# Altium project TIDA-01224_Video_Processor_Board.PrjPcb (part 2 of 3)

## Sheet TIDA-010224_Video_Processor_P02_OA7000_Image_Sensor.SchDoc: TIDA-010224_P02_OA7000_Image_Sensor
size A2; Date: Not shown in title block; ApprovedBy: Not shown in title block; CheckedBy: Not shown in title block; Author: Not shown in title block; CompanyName: Not shown in title block; DrawnBy: Sakshi Markhedkar; Engineer: Not shown in title block; Organization: Not shown in title block; Address1: Not shown in title block; Address2: Not shown in title block; Address3: Not shown in title block; Address4: Not shown in title block; DocumentNumber: 3; Revision: Use project parameter SCH_Rev; SheetNumber: 3; SheetTotal: 6; PageSetup: Record=PageOptions¦CenterHorizontal=True¦CenterVertical=True¦PrintScale=1.00¦XCorrection=1.00¦YCorrection=1.00¦PrintKind=0¦BorderSize=5000000¦LeftOffset=0¦BottomOffset=0¦Orientation=2¦PaperLength=1000¦PaperWidth=1000¦Scale=100¦PaperSource=15¦PrintQuality=600¦MediaType=1¦DitherType=10¦PaperKind=Letter¦PrintScaleMode=1
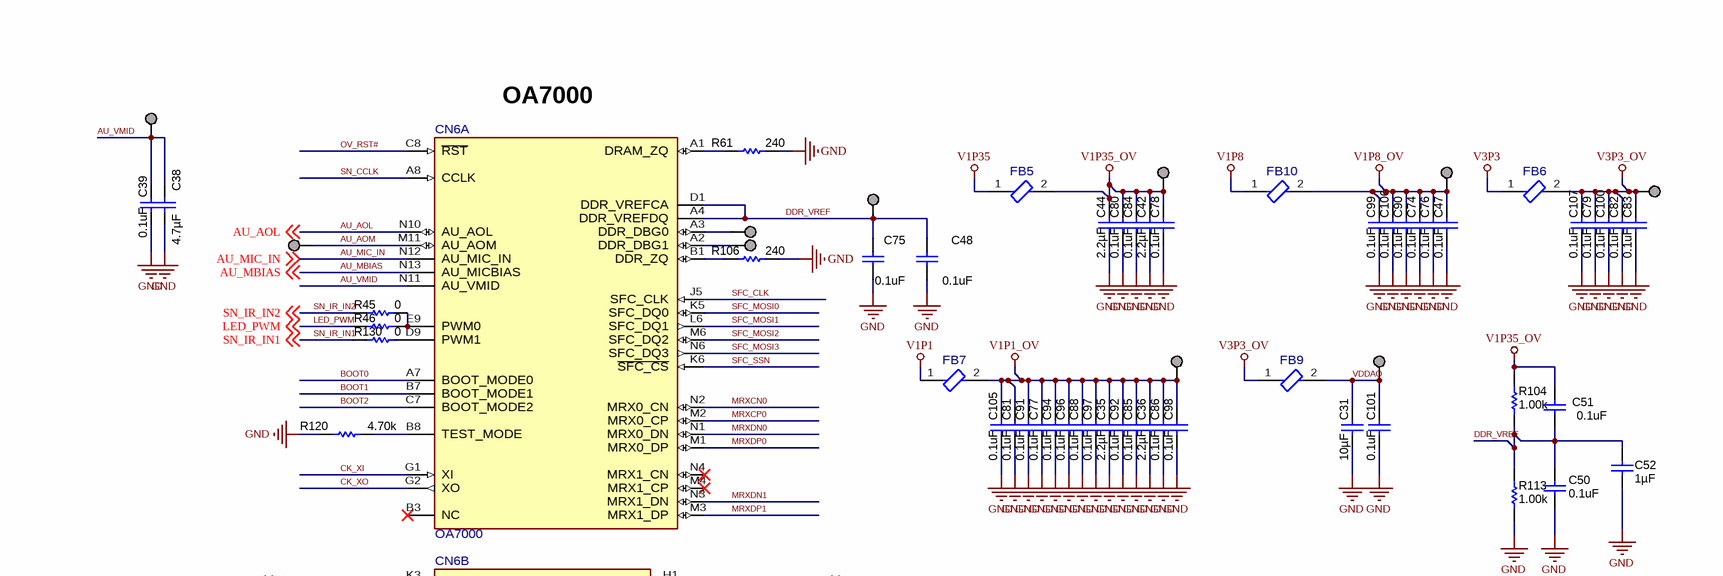
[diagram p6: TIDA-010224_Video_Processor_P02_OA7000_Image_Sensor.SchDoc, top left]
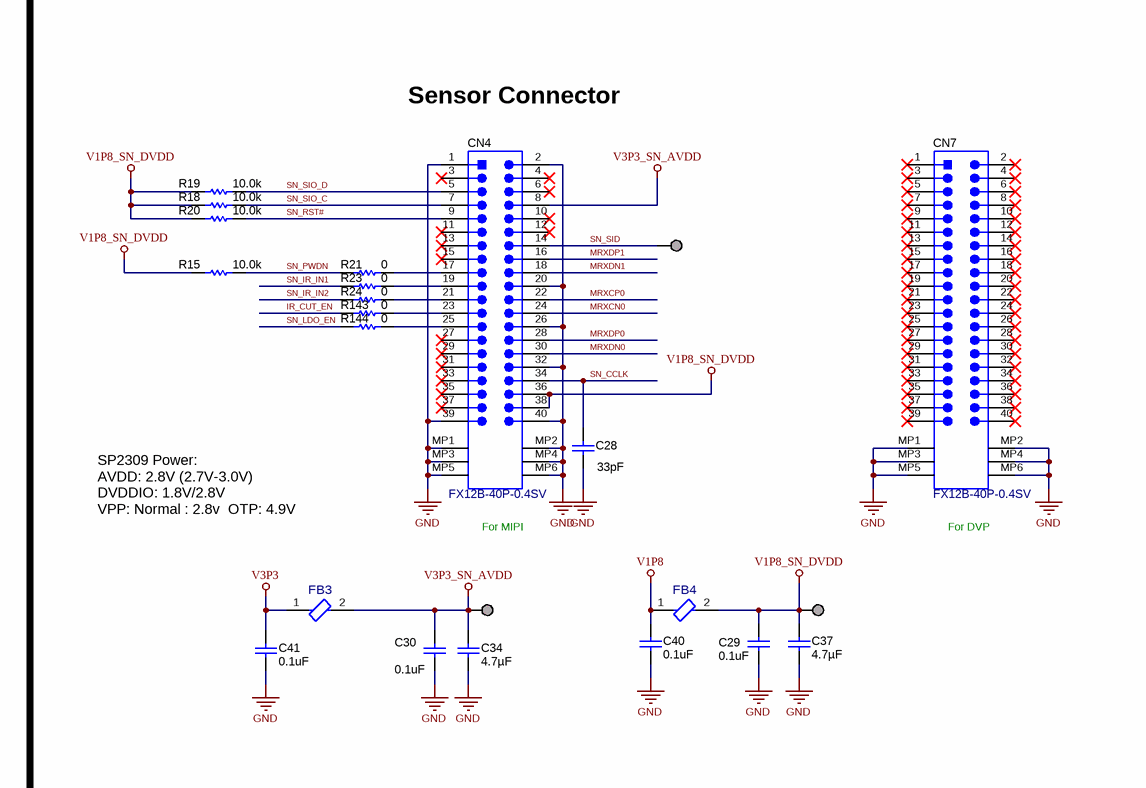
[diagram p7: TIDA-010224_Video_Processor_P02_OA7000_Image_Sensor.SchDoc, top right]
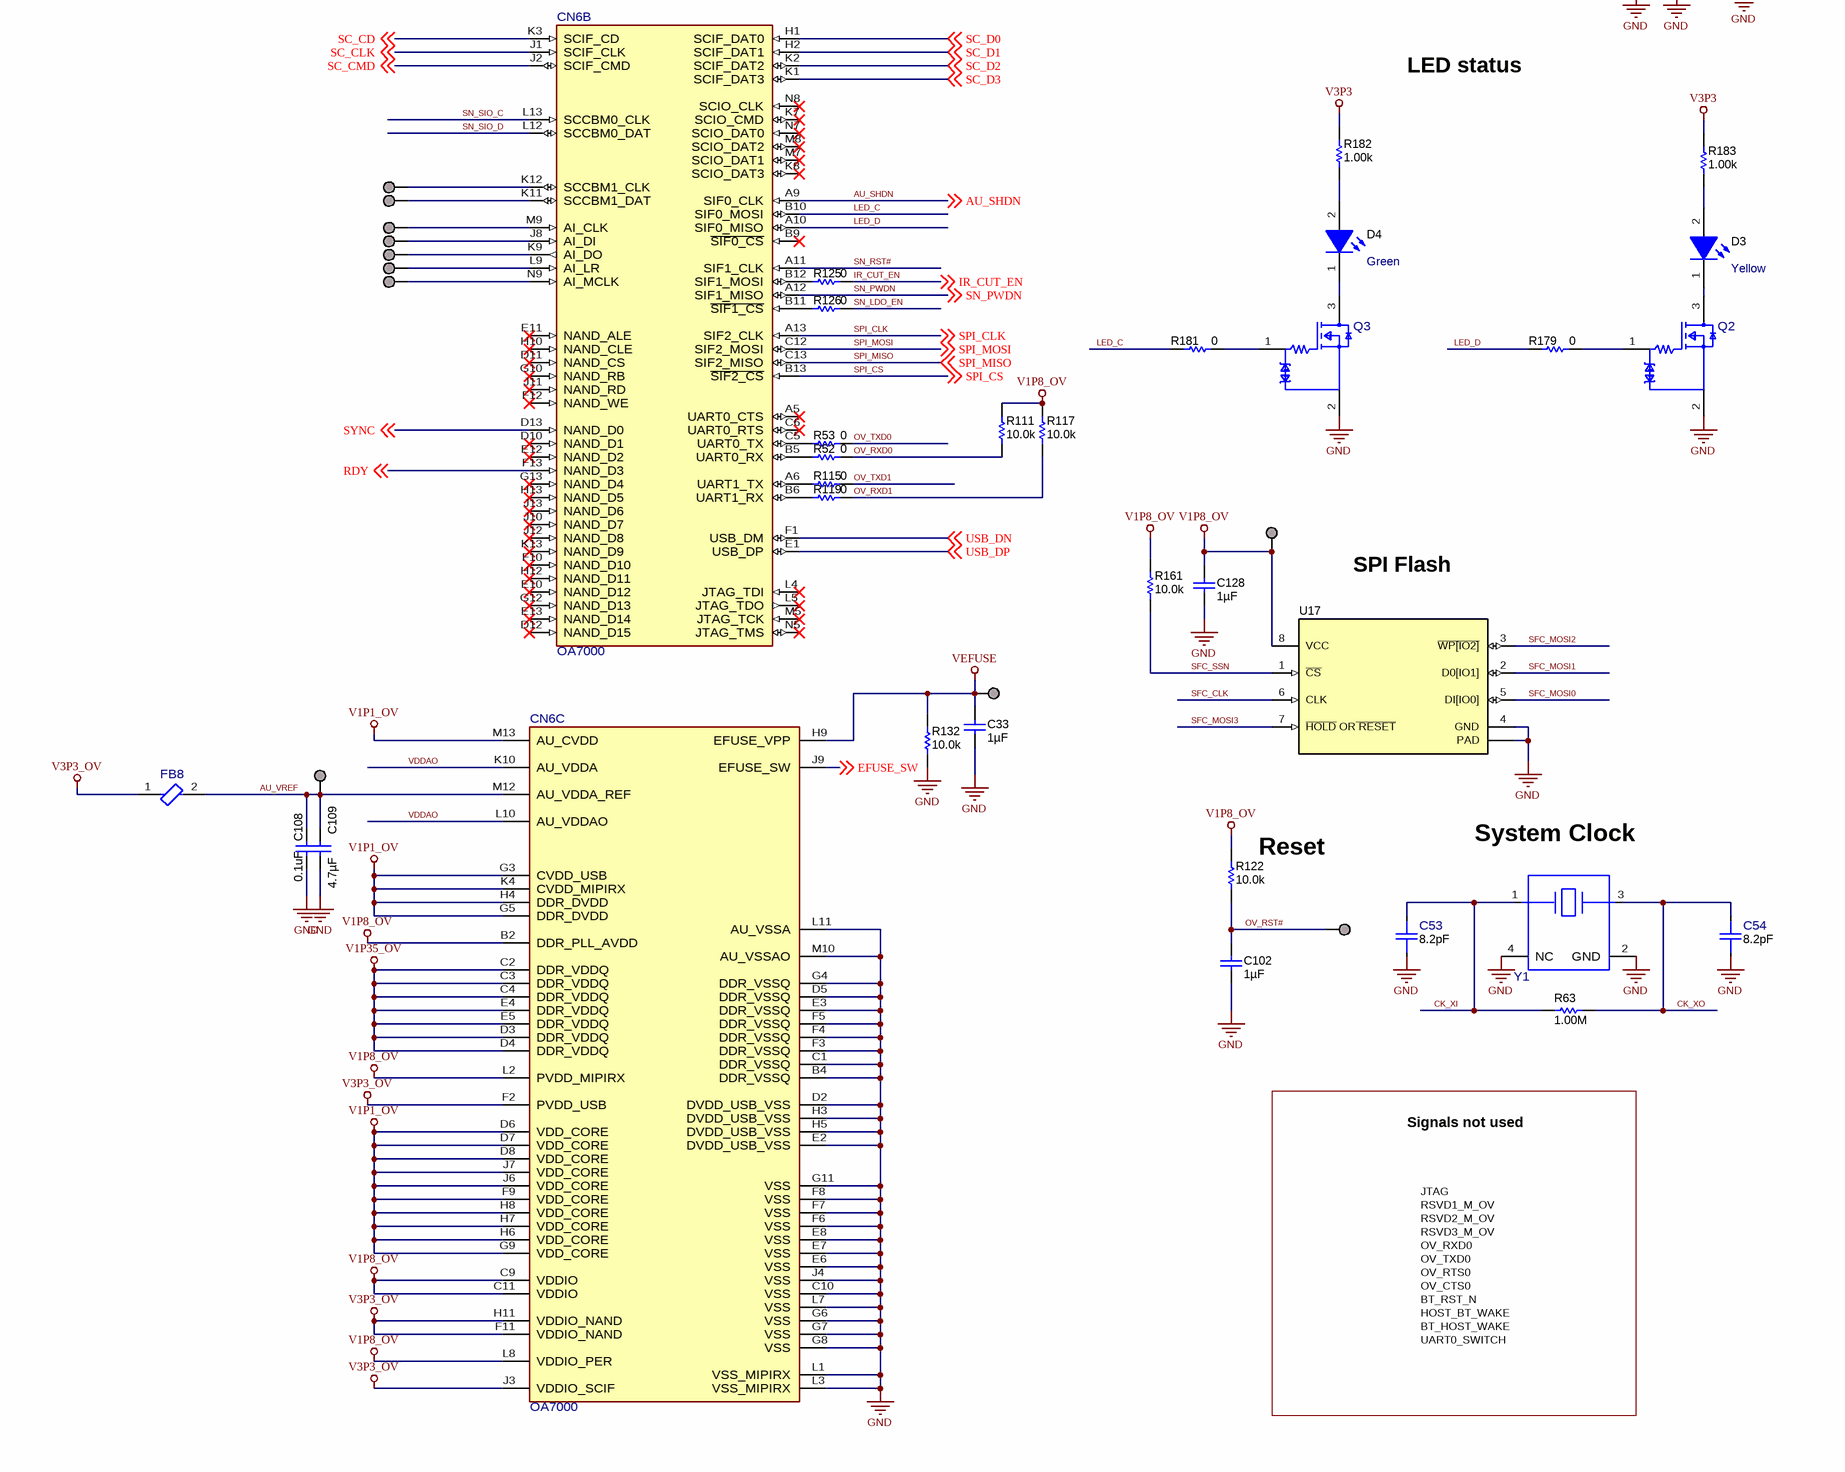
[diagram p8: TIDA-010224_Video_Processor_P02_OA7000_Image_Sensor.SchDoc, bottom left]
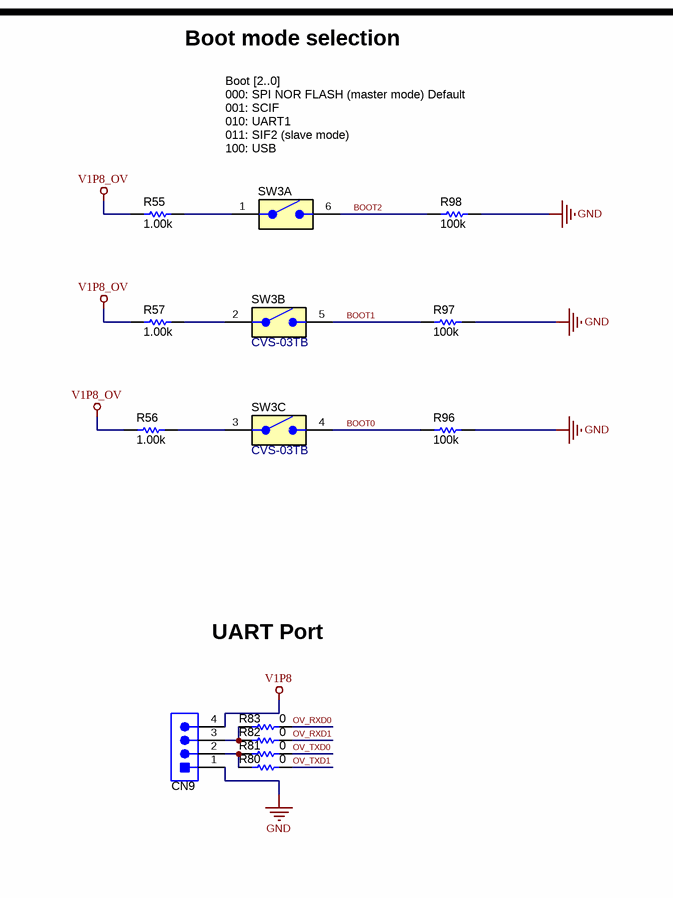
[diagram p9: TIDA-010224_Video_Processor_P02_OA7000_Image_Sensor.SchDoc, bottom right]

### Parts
AOM  TP_SM_1MM  [TP_SM_1MM]  (value not drawn)  (no BOM)
AVDD  TP_SM_1MM  [TP_SM_1MM]  (value not drawn)  (no BOM)
C  TP_SM_1MM  [TP_SM_1MM]  (value not drawn)  (no BOM)
C28  ValueDisplayed: 33pF  [0402]  (hidden comment: C1005C0G1H330J050BA)
C29  value 0.1uF  [0402]  (hidden comment: GRM155R71C104KA88D)
C30  value 0.1uF  [0402]  (hidden comment: GRM155R71C104KA88D)
C31  Cap_F: 10µF  [0805_HV]  (hidden comment: CL21B106KOQNNNE)
C33  Cap_F: 1µF  [0603]  (hidden comment: GCM188R71C105MA64D)
C34  Cap_F: 4.7µF  [0603]  (hidden comment: GRM188Z71C475KE21D)
C35  Cap_F: 2.2µF  [0603]  (hidden comment: GRM188Z71C225KE43)
C36  Cap_F: 2.2µF  [0603]  (hidden comment: GRM188Z71C225KE43)
C37  Cap_F: 4.7µF  [0603]  (hidden comment: GRM188Z71C475KE21D)
C38  Cap_F: 4.7µF  [0603]  (hidden comment: GRM188Z71C475KE21D)
C39  ValueDisplayed: 0.1uF  [0201]  (hidden comment: GRM033Z71C104KE14D)
C40  value 0.1uF  [0402]  (hidden comment: GRM155R71C104KA88D)
C41  value 0.1uF  [0402]  (hidden comment: GRM155R71C104KA88D)
C42  Cap_F: 2.2µF  [0603]  (hidden comment: GRM188Z71C225KE43)
C44  Cap_F: 2.2µF  [0603]  (hidden comment: GRM188Z71C225KE43)
C47  ValueDisplayed: 0.1uF  [0201]  (hidden comment: GRM033Z71C104KE14D)
C48  ValueDisplayed: 0.1uF  [0201]  (hidden comment: GRM033Z71C104KE14D)
C50  ValueDisplayed: 0.1uF  [0201]  (hidden comment: GRM033Z71C104KE14D)
C51  ValueDisplayed: 0.1uF  [0201]  (hidden comment: GRM033Z71C104KE14D)
C52  Cap_F: 1µF  [0603]  (hidden comment: GCM188R71C105MA64D)
C53  ValueDisplayed: 8.2pF  [FP-GRM1555C1H8R2BA01D_0402-MFG]  (hidden comment: GRM1555C1H8R2BA01D)
C54  ValueDisplayed: 8.2pF  [FP-GRM1555C1H8R2BA01D_0402-MFG]  (hidden comment: GRM1555C1H8R2BA01D)
C74  ValueDisplayed: 0.1uF  [0201]  (hidden comment: GRM033Z71C104KE14D)
C75  ValueDisplayed: 0.1uF  [0201]  (hidden comment: GRM033Z71C104KE14D)
C76  ValueDisplayed: 0.1uF  [0201]  (hidden comment: GRM033Z71C104KE14D)
C77  ValueDisplayed: 0.1uF  [0201]  (hidden comment: GRM033Z71C104KE14D)
C78  ValueDisplayed: 0.1uF  [0201]  (hidden comment: GRM033Z71C104KE14D)
C79  ValueDisplayed: 0.1uF  [0201]  (hidden comment: GRM033Z71C104KE14D)
C80  ValueDisplayed: 0.1uF  [0201]  (hidden comment: GRM033Z71C104KE14D)
C81  ValueDisplayed: 0.1uF  [0201]  (hidden comment: GRM033Z71C104KE14D)
C82  ValueDisplayed: 0.1uF  [0201]  (hidden comment: GRM033Z71C104KE14D)
C83  ValueDisplayed: 0.1uF  [0201]  (hidden comment: GRM033Z71C104KE14D)
C84  ValueDisplayed: 0.1uF  [0201]  (hidden comment: GRM033Z71C104KE14D)
C85  ValueDisplayed: 0.1uF  [0201]  (hidden comment: GRM033Z71C104KE14D)
C86  ValueDisplayed: 0.1uF  [0201]  (hidden comment: GRM033Z71C104KE14D)
C88  ValueDisplayed: 0.1uF  [0201]  (hidden comment: GRM033Z71C104KE14D)
C90  ValueDisplayed: 0.1uF  [0201]  (hidden comment: GRM033Z71C104KE14D)
C91  ValueDisplayed: 0.1uF  [0201]  (hidden comment: GRM033Z71C104KE14D)
C92  ValueDisplayed: 0.1uF  [0201]  (hidden comment: GRM033Z71C104KE14D)
C94  ValueDisplayed: 0.1uF  [0201]  (hidden comment: GRM033Z71C104KE14D)
C96  ValueDisplayed: 0.1uF  [0201]  (hidden comment: GRM033Z71C104KE14D)
C97  ValueDisplayed: 0.1uF  [0201]  (hidden comment: GRM033Z71C104KE14D)
C98  ValueDisplayed: 0.1uF  [0201]  (hidden comment: GRM033Z71C104KE14D)
C99  ValueDisplayed: 0.1uF  [0201]  (hidden comment: GRM033Z71C104KE14D)
C100  ValueDisplayed: 0.1uF  [0201]  (hidden comment: GRM033Z71C104KE14D)
C101  ValueDisplayed: 0.1uF  [0201]  (hidden comment: GRM033Z71C104KE14D)
C102  Cap_F: 1µF  [0603]  (hidden comment: GCM188R71C105MA64D)
C105  ValueDisplayed: 0.1uF  [0201]  (hidden comment: GRM033Z71C104KE14D)
C106  ValueDisplayed: 0.1uF  [0201]  (hidden comment: GRM033Z71C104KE14D)
C107  ValueDisplayed: 0.1uF  [0201]  (hidden comment: GRM033Z71C104KE14D)
C108  ValueDisplayed: 0.1uF  [0201]  (hidden comment: GRM033Z71C104KE14D)
C109  Cap_F: 4.7µF  [0603]  (hidden comment: GRM188Z71C475KE21D)
C128  Cap_F: 1µF  [0603]  (hidden comment: GCM188R71C105MA64D)
CLK  TP_SM_1MM  [TP_SM_1MM]  (value not drawn)  (no BOM)
CN4  FX12B-40P-0.4SV  [Hirose_FX12B-40P-0_4SV]
CN6  OA7000  [FP-OA7000_BGA169-IPC_C]  (parts A,B,C of 3)
CN7  FX12B-40P-0.4SV  [Hirose_FX12B-40P-0_4SV]
CN9  GRPB041VWVN-RC  [Sullins_GRPB041VWVN-RC]  (value not drawn)
D  TP_SM_1MM  [TP_SM_1MM]  (value not drawn)  (no BOM)
D3  value Yellow  [WL-SMCW_YELLOW]  (hidden comment: 150060YS75000)
D4  value Green  [WL-SMCW_GREEN]  (hidden comment: 150060GS75000)
DBG0  TP_SM_1MM  [TP_SM_1MM]  (value not drawn)  (no BOM)
DBG1  TP_SM_1MM  [TP_SM_1MM]  (value not drawn)  (no BOM)
DI  TP_SM_1MM  [TP_SM_1MM]  (value not drawn)  (no BOM)
DO  TP_SM_1MM  [TP_SM_1MM]  (value not drawn)  (no BOM)
DVDD  TP_SM_1MM  [TP_SM_1MM]  (value not drawn)  (no BOM)
FB3  BLM18KG121TN1D  [FP-BLM18KG121TN1D_0603-MFG]  (value not drawn)
FB4  BLM18KG121TN1D  [FP-BLM18KG121TN1D_0603-MFG]  (value not drawn)
FB5  BLM18KG121TN1D  [FP-BLM18KG121TN1D_0603-MFG]  (value not drawn)
FB6  BLM18KG121TN1D  [FP-BLM18KG121TN1D_0603-MFG]  (value not drawn)
FB7  BLM18KG121TN1D  [FP-BLM18KG121TN1D_0603-MFG]  (value not drawn)
FB8  BLM18KG121TN1D  [FP-BLM18KG121TN1D_0603-MFG]  (value not drawn)
FB9  BLM18KG121TN1D  [FP-BLM18KG121TN1D_0603-MFG]  (value not drawn)
FB10  BLM18KG121TN1D  [FP-BLM18KG121TN1D_0603-MFG]  (value not drawn)
LR  TP_SM_1MM  [TP_SM_1MM]  (value not drawn)  (no BOM)
MCLK  TP_SM_1MM  [TP_SM_1MM]  (value not drawn)  (no BOM)
OV_1.1V  TP_SM_1MM  [TP_SM_1MM]  (value not drawn)  (no BOM)
OV_1.8V  TP_SM_1MM  [TP_SM_1MM]  (value not drawn)  (no BOM)
OV_1.35V  TP_SM_1MM  [TP_SM_1MM]  (value not drawn)  (no BOM)
OV_3.3V  TP_SM_1MM  [TP_SM_1MM]  (value not drawn)  (no BOM)
Q2  NTS4001NT1G  [FP-NTS4001NT1G_SC-70-MFG]  (value not drawn)
Q3  NTS4001NT1G  [FP-NTS4001NT1G_SC-70-MFG]  (value not drawn)
R15  ValueDisplayed: 10.0k  [0402]  (hidden comment: ERJPA2F1002X)
R18  ValueDisplayed: 10.0k  [0402]  (hidden comment: ERJPA2F1002X)
R19  ValueDisplayed: 10.0k  [0402]  (hidden comment: ERJPA2F1002X)
R20  ValueDisplayed: 10.0k  [0402]  (hidden comment: ERJPA2F1002X)
R21  ValueDisplayed: 0  [0402S]  (hidden comment: RC0402JR-070RL)
R23  ValueDisplayed: 0  [0402S]  (hidden comment: RC0402JR-070RL)
R24  ValueDisplayed: 0  [0402S]  (hidden comment: RC0402JR-070RL)
R45  ValueDisplayed: 0  [0402S]  (hidden comment: RC0402JR-070RL)
R46  ValueDisplayed: 0  [0402S]  (hidden comment: RC0402JR-070RL)
R52  ValueDisplayed: 0  [0402S]  (hidden comment: RC0402JR-070RL)
R53  ValueDisplayed: 0  [0402S]  (hidden comment: RC0402JR-070RL)
R55  ValueDisplayed: 1.00k  [0402]  (hidden comment: CRCW04021K00FKED)
R56  ValueDisplayed: 1.00k  [0402]  (hidden comment: CRCW04021K00FKED)
R57  ValueDisplayed: 1.00k  [0402]  (hidden comment: CRCW04021K00FKED)
R61  ValueDisplayed: 240  [0402]  (hidden comment: ERJ-2RKF2400X)
R63  ValueDisplayed: 1.00M  [0402]  (hidden comment: RMCF0402FT1M00)
R80  ValueDisplayed: 0  [0402S]  (hidden comment: RC0402JR-070RL)
R81  ValueDisplayed: 0  [0402S]  (hidden comment: RC0402JR-070RL)
R82  ValueDisplayed: 0  [0402S]  (hidden comment: RC0402JR-070RL)
R83  ValueDisplayed: 0  [0402S]  (hidden comment: RC0402JR-070RL)
R96  ValueDisplayed: 100k  [0201]  (hidden comment: RC0201FR-07100KL)
R97  ValueDisplayed: 100k  [0201]  (hidden comment: RC0201FR-07100KL)
R98  ValueDisplayed: 100k  [0201]  (hidden comment: RC0201FR-07100KL)
R104  ValueDisplayed: 1.00k  [0402]  (hidden comment: CRCW04021K00FKED)
R106  ValueDisplayed: 240  [0402]  (hidden comment: ERJ-2RKF2400X)
R111  ValueDisplayed: 10.0k  [0402]  (hidden comment: ERJPA2F1002X)
R113  ValueDisplayed: 1.00k  [0402]  (hidden comment: CRCW04021K00FKED)
R115  ValueDisplayed: 0  [0402S]  (hidden comment: RC0402JR-070RL)
R117  ValueDisplayed: 10.0k  [0402]  (hidden comment: ERJPA2F1002X)
R119  ValueDisplayed: 0  [0402S]  (hidden comment: RC0402JR-070RL)
R120  ValueDisplayed: 4.70k  [0402]  (hidden comment: ERJ-2RKF4701X)
R122  ValueDisplayed: 10.0k  [0402]  (hidden comment: ERJPA2F1002X)
R125  ValueDisplayed: 0  [0402S]  (hidden comment: RC0402JR-070RL)
R126  ValueDisplayed: 0  [0402S]  (hidden comment: RC0402JR-070RL)
R130  ValueDisplayed: 0  [0402S]  (hidden comment: RC0402JR-070RL)
R132  ValueDisplayed: 10.0k  [0402]  (hidden comment: ERJPA2F1002X)
R143  ValueDisplayed: 0  [0402S]  (hidden comment: RC0402JR-070RL)
R144  ValueDisplayed: 0  [0402S]  (hidden comment: RC0402JR-070RL)
R161  ValueDisplayed: 10.0k  [0402]  (hidden comment: ERJPA2F1002X)
R179  ValueDisplayed: 0  [0402S]  (hidden comment: RC0402JR-070RL)
R181  ValueDisplayed: 0  [0402S]  (hidden comment: RC0402JR-070RL)
R182  ValueDisplayed: 1.00k  [0402]  (hidden comment: CRCW04021K00FKED)
R183  ValueDisplayed: 1.00k  [0402]  (hidden comment: CRCW04021K00FKED)
RST  TP_SM_1MM  [TP_SM_1MM]  (value not drawn)  (no BOM)
SID  TP_SM_1MM  [TP_SM_1MM]  (value not drawn)  (no BOM)
SW3  CVS-03TB  [SW_CVS-03B]  (value not drawn)  (parts A,B,C of 3)
U17  MX25U12835FZNI-10G‎  [Winbond-WSON6x5_Code P]  (value not drawn)
VCC_MEM  TP_SM_1MM  [TP_SM_1MM]  (value not drawn)  (no BOM)
VDDAO  TP_SM_1MM  [TP_SM_1MM]  (value not drawn)  (no BOM)
VeFuse  TP_SM_1MM  [TP_SM_1MM]  (value not drawn)  (no BOM)
VMID  TP_SM_1MM  [TP_SM_1MM]  (value not drawn)  (no BOM)
VREF  TP_SM_1MM  [TP_SM_1MM]  (value not drawn)  (no BOM)
VREF_AU  TP_SM_1MM  [TP_SM_1MM]  (value not drawn)  (no BOM)
Y1  ‎8Q-24.000MEEV-T‎  [FP-8Q-24.000MEIV-T_SMD-4-MFG]  (value not drawn)

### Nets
GND: C28.2 C29.2 C30.2 C31.1 C33.2 C34.2 C35.2 C36.2 C37.2 C38.2 C39.1 C40.2 C41.2 C42.2 C44.2 C47.1 C48.1 C50.1 C52.2 C53.1 C54.1 C74.1 C75.1 C76.1 C77.1 C78.1 C79.1 C80.1 C81.1 C82.1 C83.1 C84.1 C85.1 C86.1 C88.1 C90.1 C91.1 C92.1 C94.1 C96.1 C97.1 C98.1 C99.1 C100.1 C101.1 C102.2 C105.1 C106.1 C107.1 C108.1 C109.2 C128.2 CN4.1 CN4.2 CN4.20 CN4.26 CN4.32 CN4.39 CN4.40 CN4.MP1 CN4.MP2 CN4.MP3 CN4.MP4 CN4.MP5 CN4.MP6 CN6.B4(DDR_VSSQ) CN6.C1(DDR_VSSQ) CN6.C10(VSS) CN6.D2(DVDD_USB_VSS) CN6.D5(DDR_VSSQ) CN6.E2(DVDD_USB_VSS) CN6.E3(DDR_VSSQ) CN6.E6(VSS) CN6.E7(VSS) CN6.E8(VSS) CN6.F3(DDR_VSSQ) CN6.F4(DDR_VSSQ) CN6.F5(DDR_VSSQ) CN6.F6(VSS) CN6.F7(VSS) CN6.F8(VSS) CN6.G4(DDR_VSSQ) CN6.G6(VSS) CN6.G7(VSS) CN6.G8(VSS) CN6.G11(VSS) CN6.H3(DVDD_USB_VSS) CN6.H5(DVDD_USB_VSS) CN6.J4(VSS) CN6.L1(VSS_MIPIRX) CN6.L3(VSS_MIPIRX) CN6.L7(VSS) CN6.L11(AU_VSSA) CN6.M10(AU_VSSAO) CN7.MP1 CN7.MP2 CN7.MP3 CN7.MP4 CN7.MP5 CN7.MP6 CN9.1 Q2.2(Source) Q3.2(Source) R61.2 R96.2 R97.2 R98.2 R106.2 R113.1 R120.1 R132.1 U17.4(GND) U17.9(PAD) Y1.2(GND) Y1.4(NC)
V1P1: FB7.1
V1P1_OV: C35.1 C36.1 C77.2 C81.2 C85.2 C86.2 C88.2 C91.2 C92.2 C94.2 C96.2 C97.2 C98.2 C105.2 CN6.D6(VDD_CORE) CN6.D7(VDD_CORE) CN6.D8(VDD_CORE) CN6.F9(VDD_CORE) CN6.G3(CVDD_USB) CN6.G5(DDR_DVDD) CN6.G9(VDD_CORE) CN6.H4(DDR_DVDD) CN6.H6(VDD_CORE) CN6.H7(VDD_CORE) CN6.H8(VDD_CORE) CN6.J6(VDD_CORE) CN6.J7(VDD_CORE) CN6.K4(CVDD_MIPIRX) CN6.M13(AU_CVDD) FB7.2 OV_1.1V.1
V1P8: C40.1 CN9.4 FB4.1 FB10.1
V1P8_OV: C47.2 C74.2 C76.2 C90.2 C99.2 C106.2 C128.1 CN6.B2(DDR_PLL_AVDD) CN6.C9(VDDIO) CN6.C11(VDDIO) CN6.L2(PVDD_MIPIRX) CN6.L8(VDDIO_PER) FB10.2 OV_1.8V.1 R55.2 R56.2 R57.2 R111.2 R117.2 R122.2 R161.2 U17.8(VCC) VCC_MEM.1
V1P8_SN_DVDD: C29.1 C37.1 CN4.36 CN4.38 DVDD.1 FB4.2 R15.2 R18.2 R19.2 R20.2
V1P35: FB5.1
V1P35_OV: C42.1 C44.1 C51.2 C78.2 C80.2 C84.2 CN6.C2(DDR_VDDQ) CN6.C3(DDR_VDDQ) CN6.C4(DDR_VDDQ) CN6.D3(DDR_VDDQ) CN6.D4(DDR_VDDQ) CN6.E4(DDR_VDDQ) CN6.E5(DDR_VDDQ) FB5.2 OV_1.35V.1 R104.2
V3P3: C41.1 FB3.1 FB6.1 R182.2 R183.2
V3P3_OV: C79.2 C82.2 C83.2 C100.2 C107.2 CN6.F2(PVDD_USB) CN6.F11(VDDIO_NAND) CN6.H11(VDDIO_NAND) CN6.J3(VDDIO_SCIF) FB6.2 FB8.1 FB9.1 OV_3.3V.1
V3P3_SN_AVDD: AVDD.1 C30.1 C34.1 CN4.8 FB3.2
VEFUSE: C33.1 CN6.H9(EFUSE_VPP) R132.2 VeFuse.1
AU_AOL: CN6.N10(AU_AOL) ; off-sheet AU_AOL
AU_AOM: AOM.1 CN6.M11(AU_AOM)
AU_MBIAS: CN6.N13(AU_MICBIAS) ; off-sheet AU_MBIAS
AU_MIC_IN: CN6.N12(AU_MIC_IN) ; off-sheet AU_MIC_IN
AU_SHDN: CN6.A9(SIF0_CLK) ; off-sheet AU_SHDN
AU_VMID: C38.1 C39.2 CN6.N11(AU_VMID) VMID.1
AU_VREF: C108.2 C109.1 CN6.M12(AU_VDDA_REF) FB8.2 VREF_AU.1
BOOT0: CN6.A7(BOOT_MODE0) R96.1 SW3.4
BOOT1: CN6.B7(BOOT_MODE1) R97.1 SW3.5
BOOT2: CN6.C7(BOOT_MODE2) R98.1 SW3.6
CK_XI: C53.2 CN6.G1(XI) R63.1 Y1.1
CK_XO: C54.2 CN6.G2(XO) R63.2 Y1.3
DDR_VREF: C48.2 C50.2 C51.1 C52.1 C75.2 CN6.A4(DDR_VREFDQ) CN6.D1(DDR_VREFCA) R104.1 R113.2 VREF.1
EFUSE_SW: CN6.J9(EFUSE_SW) ; off-sheet EFUSE_SW
IR_CUT_EN: R125.2 R143.1 ; off-sheet IR_CUT_EN
LED_C: CN6.B10(SIF0_MOSI) R181.1
LED_D: CN6.A10(SIF0_MISO) R179.1
LED_PWM: R46.1 ; off-sheet LED_PWM
MRXCN0: CN4.24 CN6.N2(MRX0_CN)
MRXCP0: CN4.22 CN6.M2(MRX0_CP)
MRXDN0: CN4.30 CN6.N1(MRX0_DN)
MRXDN1: CN4.18 CN6.N3(MRX1_DN)
MRXDP0: CN4.28 CN6.M1(MRX0_DP)
MRXDP1: CN4.16 CN6.M3(MRX1_DP)
OV_RST#: C102.1 CN6.C8(~{RST}) R122.1 RST.1
OV_RXD0: R52.2 R83.2 R111.1
OV_RXD1: R82.2 R117.1 R119.2
OV_TXD0: R53.2 R81.2
OV_TXD1: R80.2 R115.2
RDY: CN6.F13(NAND_D3) ; off-sheet RDY
SC_CD: CN6.K3(SCIF_CD) ; off-sheet SC_CD
SC_CLK: CN6.J1(SCIF_CLK) ; off-sheet SC_CLK
SC_CMD: CN6.J2(SCIF_CMD) ; off-sheet SC_CMD
SC_D0: CN6.H1(SCIF_DAT0) ; off-sheet SC_D0
SC_D1: CN6.H2(SCIF_DAT1) ; off-sheet SC_D1
SC_D2: CN6.K2(SCIF_DAT2) ; off-sheet SC_D2
SC_D3: CN6.K1(SCIF_DAT3) ; off-sheet SC_D3
SFC_CLK: CN6.J5(SFC_CLK) U17.6(CLK)
SFC_MOSI0: CN6.K5(SFC_DQ0) U17.5(DI[IO0])
SFC_MOSI1: CN6.L6(SFC_DQ1) U17.2(D0[IO1])
SFC_MOSI2: CN6.M6(SFC_DQ2) U17.3(~{WP[IO2]})
SFC_MOSI3: CN6.N6(SFC_DQ3) U17.7(~{HOLD}_OR~{_RESET})
SFC_SSN: CN6.K6(~{SFC_CS}) R161.1 U17.1(~{CS})
SN_CCLK: C28.1 CN4.34 CN6.A8(CCLK)
SN_IR_IN1: R23.1 R130.1 ; off-sheet SN_IR_IN1
SN_IR_IN2: R24.1 R45.1 ; off-sheet SN_IR_IN2
SN_LDO_EN: R126.2 R144.1
SN_PWDN: CN6.A12(SIF1_MISO) R15.1 R21.1 ; off-sheet SN_PWDN
SN_RST#: CN4.9 CN6.A11(SIF1_CLK) R20.1
SN_SID: CN4.14 SID.1
SN_SIO_C: CN4.7 CN6.L13(SCCBM0_CLK) R18.1
SN_SIO_D: CN4.5 CN6.L12(SCCBM0_DAT) R19.1
SPI_CLK: CN6.A13(SIF2_CLK) ; off-sheet SPI_CLK
SPI_CS: CN6.B13(~{SIF2_CS}) ; off-sheet SPI_CS
SPI_MISO: CN6.C13(SIF2_MISO) ; off-sheet SPI_MISO
SPI_MOSI: CN6.C12(SIF2_MOSI) ; off-sheet SPI_MOSI
SYNC: CN6.D13(NAND_D0) ; off-sheet SYNC
USB_DN: CN6.F1(USB_DM) ; off-sheet USB_DN
USB_DP: CN6.E1(USB_DP) ; off-sheet USB_DP
VDDAO: C31.2 C101.2 CN6.K10(AU_VDDA) CN6.L10(AU_VDDAO) FB9.2 VDDAO.1
NetC_1: C.1 CN6.K12(SCCBM1_CLK)
NetCLK_1: CLK.1 CN6.M9(AI_CLK)
NetCN4_17: CN4.17 R21.2
NetCN4_19: CN4.19 R23.2
NetCN4_21: CN4.21 R24.2
NetCN4_23: CN4.23 R143.2
NetCN4_25: CN4.25 R144.2
NetCN6_A1: CN6.A1(DRAM_ZQ) R61.1
NetCN6_A2: CN6.A2(DDR_DBG1) DBG1.1
NetCN6_A3: CN6.A3(DDR_DBG0) DBG0.1
NetCN6_A6: CN6.A6(UART1_TX) R115.1
NetCN6_B1: CN6.B1(DDR_ZQ) R106.1
NetCN6_B5: CN6.B5(UART0_RX) R52.1
NetCN6_B6: CN6.B6(UART1_RX) R119.1
NetCN6_B8: CN6.B8(TEST_MODE) R120.2
NetCN6_B11: CN6.B11(~{SIF1_CS}) R126.1
NetCN6_B12: CN6.B12(SIF1_MOSI) R125.1
NetCN6_C5: CN6.C5(UART0_TX) R53.1
NetCN6_D9: CN6.D9(PWM1) R130.2
NetCN6_E9: CN6.E9(PWM0) R45.2 R46.2
NetCN6_J8: CN6.J8(AI_DI) DI.1
NetCN6_K9: CN6.K9(AI_DO) DO.1
NetCN6_K11: CN6.K11(SCCBM1_DAT) D.1
NetCN6_L9: CN6.L9(AI_LR) LR.1
NetCN6_N9: CN6.N9(AI_MCLK) MCLK.1
NetCN9_2: CN9.2 R80.1 R81.1
NetCN9_3: CN9.3 R82.1 R83.1
NetD3_1: D3.1(K) Q2.3(Drain)
NetD3_2: D3.2(A) R183.1
NetD4_1: D4.1(K) Q3.3(Drain)
NetD4_2: D4.2(A) R182.1
NetQ2_1: Q2.1(Gate) R179.2
NetQ3_1: Q3.1(Gate) R181.2
NetR55_1: R55.1 SW3.1
NetR56_1: R56.1 SW3.3
NetR57_1: R57.1 SW3.2

Not connected (* = marked no-connect by the designer): CN4 3* 4* 6* 10* 11* 12* 13* 15* 27* 29* 31* 33* 35* 37*; CN6 A5(UART0_CTS)* B3(NC)* B9(~{SIF0_CS})* C6(UART0_RTS)* D10(NAND_D1)* D11(NAND_CS)* D12(NAND_D15)* E10(NAND_D12)* E11(NAND_ALE)* E12(NAND_D2)* E13(NAND_D14)* F10(NAND_D10)* F12(NAND_WE)* G10(NAND_RB)* G12(NAND_D13)* G13(NAND_D4)* H10(NAND_CLE)* H12(NAND_D11)* H13(NAND_D5)* J10(NAND_D7)* J11(NAND_RD)* J12(NAND_D8)* J13(NAND_D6)* K7(SCIO_CMD)* K8(SCIO_DAT3)* K13(NAND_D9)* L4(JTAG_TDI)* L5(JTAG_TDO)* M4(MRX1_CP)* M5(JTAG_TCK)* M7(SCIO_DAT1)* M8(SCIO_DAT2)* N4(MRX1_CN)* N5(JTAG_TMS)* N7(SCIO_DAT0)* N8(SCIO_CLK)*; CN7 1* 2* 3* 4* 5* 6* 7* 8* 9* 10* 11* 12* 13* 14* 15* 16* 17* 18* 19* 20* 21* 22* 23* 24* 25* 26* 27* 28* 29* 30* 31* 32* 33* 34* 35* 36* 37* 38* 39* 40*

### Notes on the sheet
- (near CN6) OA7000
- Sensor Connector
- (near CN4) For MIPI
- (near CN7) For DVP
- LED status
- SP2309 Power:
  AVDD: 2.8V (2.7V-3.0V)
  DVDDIO: 1.8V/2.8V
  VPP: Normal : 2.8v  OTP: 4.9V
- Boot mode selection
- SPI Flash
- Boot [2..0]
  000: SPI NOR FLASH (master mode) Default
  001: SCIF
  010: UART1
  011: SIF2 (slave mode)
  100: USB
- (near R122) Reset
- System Clock
- UART Port
- Signals not used
- JTAG
- RSVD1_M_OV
- RSVD2_M_OV
- RSVD3_M_OV
- OV_RXD0
- OV_TXD0
- OV_RTS0
- OV_CTS0
- BT_RST_N
- HOST_BT_WAKE
- BT_HOST_WAKE
- UART0_SWITCH

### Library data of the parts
AOM AVDD C CLK D DBG0 DBG1 DI DO DVDD LR MCLK OV_1.1V OV_1.8V OV_1.35V OV_3.3V RST SID VCC_MEM VDDAO VeFuse VMID VREF VREF_AU = CMP-0003825-1: 1mm Test Point, SMT; Manufacturer: Any
C28 = CMP-0006250-2: CAP, CERM, 33 pF, 50 V, +/- 5%, C0G/NP0, 0402; Manufacturer: TDK; TaMin_C: -55°C; Polarized: N; SizeAreaWB_mm2: 3; Value1: Unknown; U/M: EA; Value: 33pF; TaMax_C: 125°C; SizeZ_mm: 0.6; SizeX_mm: 1; SizeY_mm: 0.5; Value2: 50V; AEC Category: Q200
C29 C30 C40 C41 = Cap: CAP CER 0.1UF 16V 10% X7R 0402; Manufacturer: Murata Electronics North America
C31 = CMP-0007995-1: CAP, CERM, 10 uF, 16 V, +/- 10%, X7R, 0805; Manufacturer: Samsung Electro-Mechanics; TaMin_C: -55°C; Polarized: N; SizeAreaWB_mm2: 6.75; Value1: Unknown; U/M: EA; Value: 10uF; TaMax_C: 125°C; SizeZ_mm: 1.45; SizeX_mm: 2; SizeY_mm: 1.25; Cap_Case: 0805; Value2: 16V; SizeArea_mm2: 2.5; AEC Category: Q200
C33 C52 C102 C128 = CMP-0007137-1: CAP, CERM, 1 uF, 16 V, +/- 20%, X7R, AEC-Q200 Grade 1, 0603; Manufacturer: MuRata; TaMin_C: -55°C; Polarized: N; SizeAreaWB_mm2: 4.68; Value1: Unknown; U/M: EA; Value: 1uF; TaMax_C: 125°C; SizeZ_mm: 1; SizeX_mm: 1.6; SizeY_mm: 0.8; Value2: 16V; SizeArea_mm2: 1.28; AEC Qualified: Y; AEC Category: Q200
C34 C37 C38 C109 = CMP-0064936-4: CAP, CERM, 4.7 uF, 16 V,+/- 10%, X7R, 0603; Manufacturer: MuRata; TaMin_C: -55°C; Polarized: N; SizeAreaWB_mm2: 4.68; Value1: Unknown; U/M: EA; Value: 4.7uF; TaMax_C: 125°C; SizeZ_mm: 1; SizeX_mm: 1.6; SizeY_mm: 0.8; Value2: 16V; SizeArea_mm2: 1.28; AEC Category: Q200
C35 C36 C42 C44 = CMP-0007499-1: CAP, CERM, 2.2 uF, 16 V, +/- 10%, X7R, 0603; Manufacturer: MuRata; TaMin_C: -55°C; Polarized: N; SizeAreaWB_mm2: 4.68; Value1: Unknown; U/M: EA; Value: 2.2uF; TaMax_C: 125°C; SizeZ_mm: 1; SizeX_mm: 1.6; SizeY_mm: 0.8; Value2: 16V; SizeArea_mm2: 1.28; AEC Category: Q200
C39 C47 C48 C50 C51 C74-C86 C88 C90-C92 C94 C96-C101 C105-C108 = CMP-0064970-1: CAP, CERM, 0.1 uF, 16 V,+/- 10%, X7R, 0201; Manufacturer: MuRata; TaMin_C: -55°C; Polarized: N; SizeAreaWB_mm2: 2.08; Value1: Unknown; U/M: EA; Value: 0.1uF; TaMax_C: 125°C; SizeZ_mm: 0.26; SizeX_mm: 0.6; SizeY_mm: 0.3; Value2: 16V; SizeArea_mm2: 0.18; Cap_F: 100nF; AEC Category: Q200
C53 C54 = CMP-0089999-1: 8.2pF ±0.1pF 50V Ceramic Capacitor C0G, NP0 0402 (1005 Metric); Manufacturer: Murata Electronics North America; SizeZ_mm: 0.55mm; TempCo: 30ppm/°C; AEC Qualified: No
CN4 CN7 = CMP-0079908-1: Plug, 0.4 mm, 20x2, Gold, SMT; Manufacturer: Hirose Electric Co. Ltd.; Pitch_mm: 0.4; Gender: Male; Cert_UL: Y; Row_Count: 2
CN6 = CMP-0089425-1: Camera Video Processor; Manufacturer: Omnivision; AEC Qualified: No; Min Supply Voltage: 1.045V; SizeZ_mm: 1.6mm; Standoff Height: 0.16mm; Nominal Supply Current: 233mA; Max Supply Voltage: 3.6V
CN9 = GRPB041VWVN-RC: Header, 50mil, 4x1, Gold, TH; Manufacturer: Sullins Connector Solutions; SymbolCreator: a0412235
D3 = CMP-0002892-3: LED, Yellow, SMD; Manufacturer: Wurth Elektronik; Value1: W; Vf_V: 2V; Type: AlInGaP; Io_A: 20mA
D4 = CMP-0002905-2: LED, Green, SMD; Manufacturer: Wurth Elektronik; Value1: W; Type: InGaN; Value2: 3.2V; Io_A: 20mA; Angle: 140; Tjmax_C: 85°C
FB3-FB10 = CMP-0089995-1: 120 Ohms @ 100MHz 1 Power Line Ferrite Bead 0603 (1608 Metric) 3A 30mOhm; Manufacturer: Murata; DCR_ohm: 0.03; Impedance At Frequency: 120Ω @ 100MHz; Tolerance_%: 25%; AEC Qualified: No; SizeZ_mm: 0.75mm
Q2 Q3 = CMP-0089424-1: N-Channel 30V 270mA (Ta) 330mW (Ta) Surface Mount SC-70-3 (SOT323); Manufacturer: On Semiconductor; Threshold Vgs Max: 1.5V; Ciiva Ids: 830112; TJmax_C: +150°C; Turn On Delay Time: 17ns; Transconductance: 0.08S; Vgs_V: 20V; Standoff Height: 0mm; SizeZ_mm: 1mm; Input Capacitace At Vds: 20pF @ 5V; Import Ts: 1521845563; Turn Off Delay Time: 94ns; Pulse Drain Current: 800mA; QgTyp_nC: 0.9nC @ 5V; Number Of N Channels: 1; Threshold Vgs Min: 0.8V; AEC Qualified: No; Typ Forward Diode Voltage: 0.65V; ChMode: False; Reverse Recovery Time: 5ns; VdsMax_V: 700mV
R15 R18-R20 R111 R117 R122 R132 R161 = CMP-0078779-1: RES, 10.0 k, 1%, 0.2 W, AEC-Q200 Grade 0, 0402; Manufacturer: Panasonic; Value_Code: 10k0; SizeArea_mm2: 0.5; AEC Qualified: Y; AEC Category: Q200; Res_ohm: 10k; Value: 10.0k; SizeZ_mm: 0.6; EIA_Code: E96; TempCo: 100 ppm/C; AEC Grade: 0; Power_W: 200mW; VDC_V: 50V; Value2: 0.2W; SizeX_mm: 1
R21 R23 R24 R45 R46 R52 R53 R80-R83 R115 R119 R125 R126 R130 R143 R144 R179 R181 = CMP-0027004-2: RES, 0, 5%, 0.063 W, 0402; Manufacturer: Yageo America; Power_W: 63mW; TempCo: 200 ppm/C; Value_Code: 0000; U/M: EA; Value: 0; EIA_Code: E24; SizeX_mm: 1; SizeY_mm: 0.5; SizeZ_mm: 0.6; Value2: 0.063W; VDC_V: 50V; AEC Category: Q200
R55-R57 R104 R113 R182 R183 = CMP-0026071-3: RES, 1.00 k, 1%, 0.063 W, AEC-Q200 Grade 0, 0402; Manufacturer: Vishay-Dale; Power_W: 63mW; TempCo: 100 ppm/C; Value_Code: 1k00; Value: 1.00k; EIA_Code: E96; Res_ohm: 1k; SizeX_mm: 1; SizeY_mm: 0.5; SizeZ_mm: 0.6; Value2: 0.063W; AEC Qualified: Y; VDC_V: 50V; AEC Category: Q200; AEC Grade: 0
R61 R106 = CMP-0026684-1: RES, 240, 1%, 0.1 W, AEC-Q200 Grade 0, 0402; Manufacturer: Panasonic; Power_W: 100mW; TempCo: 100 ppm/C; Value_Code: 240R; U/M: EA; Value: 240; SizeX_mm: 1; SizeY_mm: 0.5; SizeZ_mm: 0.6; Value2: 0.1W; AEC Qualified: Y; VDC_V: 50V; AEC Grade: 0; AEC Category: Q200
R63 = CMP-0026757-1: RES, 1.00 M, 1%, 0.063 W, AEC-Q200 Grade 0, 0402; Manufacturer: Stackpole Electronics Inc; Power_W: 63mW; TempCo: 100 ppm/C; Value_Code: 1M00; U/M: EA; Value: 1.00Meg; EIA_Code: E96; Res_ohm: 1M; SizeX_mm: 1; SizeY_mm: 0.5; SizeZ_mm: 0.6; Value2: 0.063W; AEC Qualified: Y; VDC_V: 50V; AEC Grade: 0; AEC Category: Q200
R96-R98 = CMP-0027293-2: RES, 100 k, 1%, 0.05 W, 0201; Manufacturer: Yageo America; Power_W: 50mW; TempCo: 200 ppm/C; U/M: EA; Value: 100k; EIA_Code: E96; SizeX_mm: 0.6; SizeY_mm: 0.3; SizeZ_mm: 0.26; Value2: 0.05W; SizeArea_mm2: 0.18; AEC Qualified: N; VDC_V: 25V; AEC Category: Q200
R120 = CMP-0026700-1: RES, 4.70 k, 1%, 0.1 W, 0402; Manufacturer: Panasonic; Power_W: 100mW; TempCo: 100 ppm/C; Value_Code: 4k70; U/M: EA; Value: 4.70k; Res_ohm: 4.7k; SizeX_mm: 1; SizeY_mm: 0.5; SizeZ_mm: 0.6; Value2: 0.1W; VDC_V: 50V; AEC Category: Q200
SW3 = CMP-0002165-2: DIP Switch, SPST, 3Pos, Slide, SMT; Manufacturer: Copal Electronics; CurrentRating_mA: 100A; SwitchFunction: Off-On; VDC_V: 6V; PositionCount: 3
U17 = CMP-0080013-1: 1.8V 128-BIT SERIAL FLASH MEMORY WITH DUAL QUAD SPI & QPI, WSON8; Manufacturer: Macronix
Y1 = CMP-0089415-1: Crystals 1.6x1.2 Seam Seal MHz Quartz Xtal -4pad / Ceramic, +/-10ppm @25C, +/-20ppm (-40 to 85C), 8pF; Manufacturer: TXC Corporation; Frequency_Fixed: 24MHz; Esr: 100; Frequency Tolerance: 10ppm; SizeZ_mm: 0.4mm; Frequency Stability: 20ppm; AEC Qualified: No

## Sheet TIDA-010224_Video_Processor_P03_CC3235MODA_WIFI_Launchpad.SchDoc: TIDA-010224_P03_Wi-Fi_Launchpad
size A2; Date: Not shown in title block; ApprovedBy: Not shown in title block; CheckedBy: Not shown in title block; Author: Not shown in title block; CompanyName: Not shown in title block; DrawnBy: Sakshi Markhedkar; Engineer: Not shown in title block; Organization: Not shown in title block; Address1: Not shown in title block; Address2: Not shown in title block; Address3: Not shown in title block; Address4: Not shown in title block; DocumentNumber: 4; Revision: Use project parameter SCH_Rev; SheetNumber: 4; SheetTotal: 6; PageSetup: Record=PageOptions¦CenterHorizontal=True¦CenterVertical=True¦PrintScale=1.00¦XCorrection=1.00¦YCorrection=1.00¦PrintKind=0¦BorderSize=5000000¦LeftOffset=0¦BottomOffset=0¦Orientation=2¦PaperLength=1000¦PaperWidth=1000¦Scale=100¦PaperSource=15¦PrintQuality=600¦MediaType=1¦DitherType=10¦PaperKind=Letter¦PrintScaleMode=1
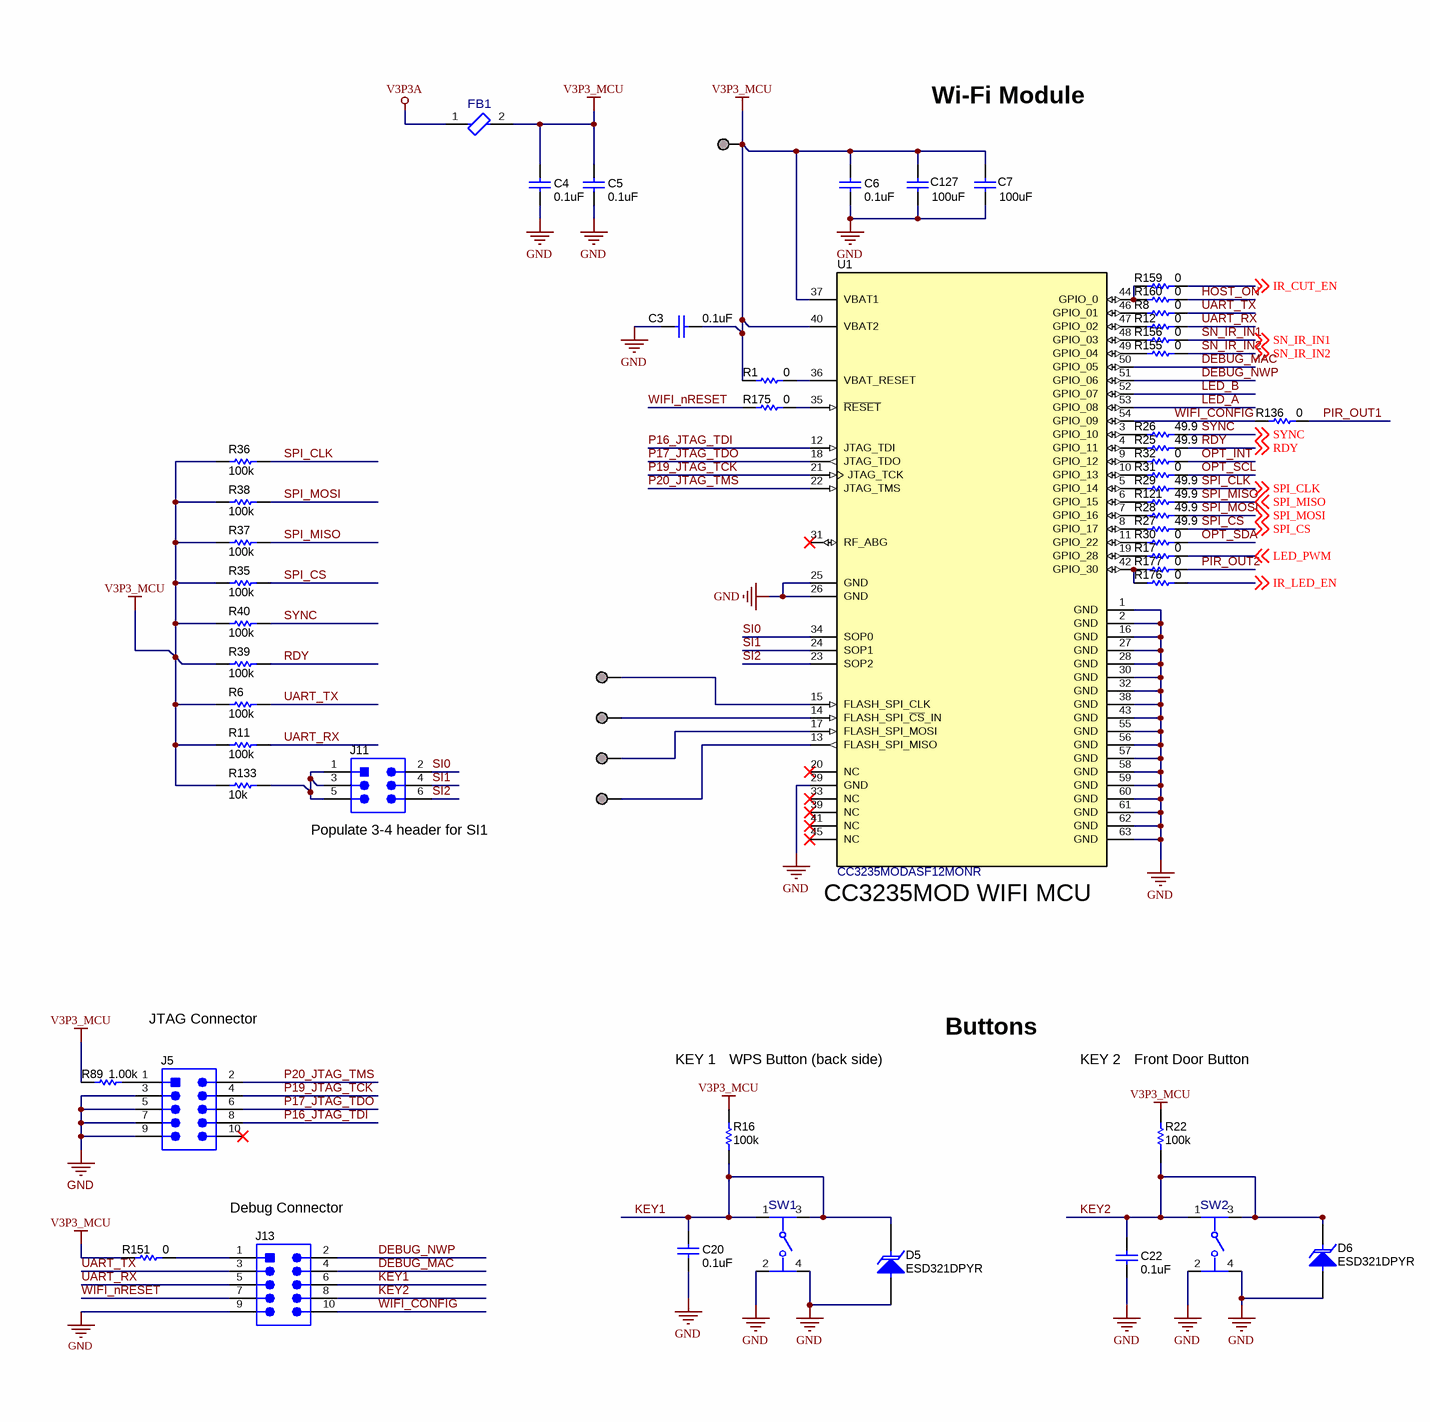
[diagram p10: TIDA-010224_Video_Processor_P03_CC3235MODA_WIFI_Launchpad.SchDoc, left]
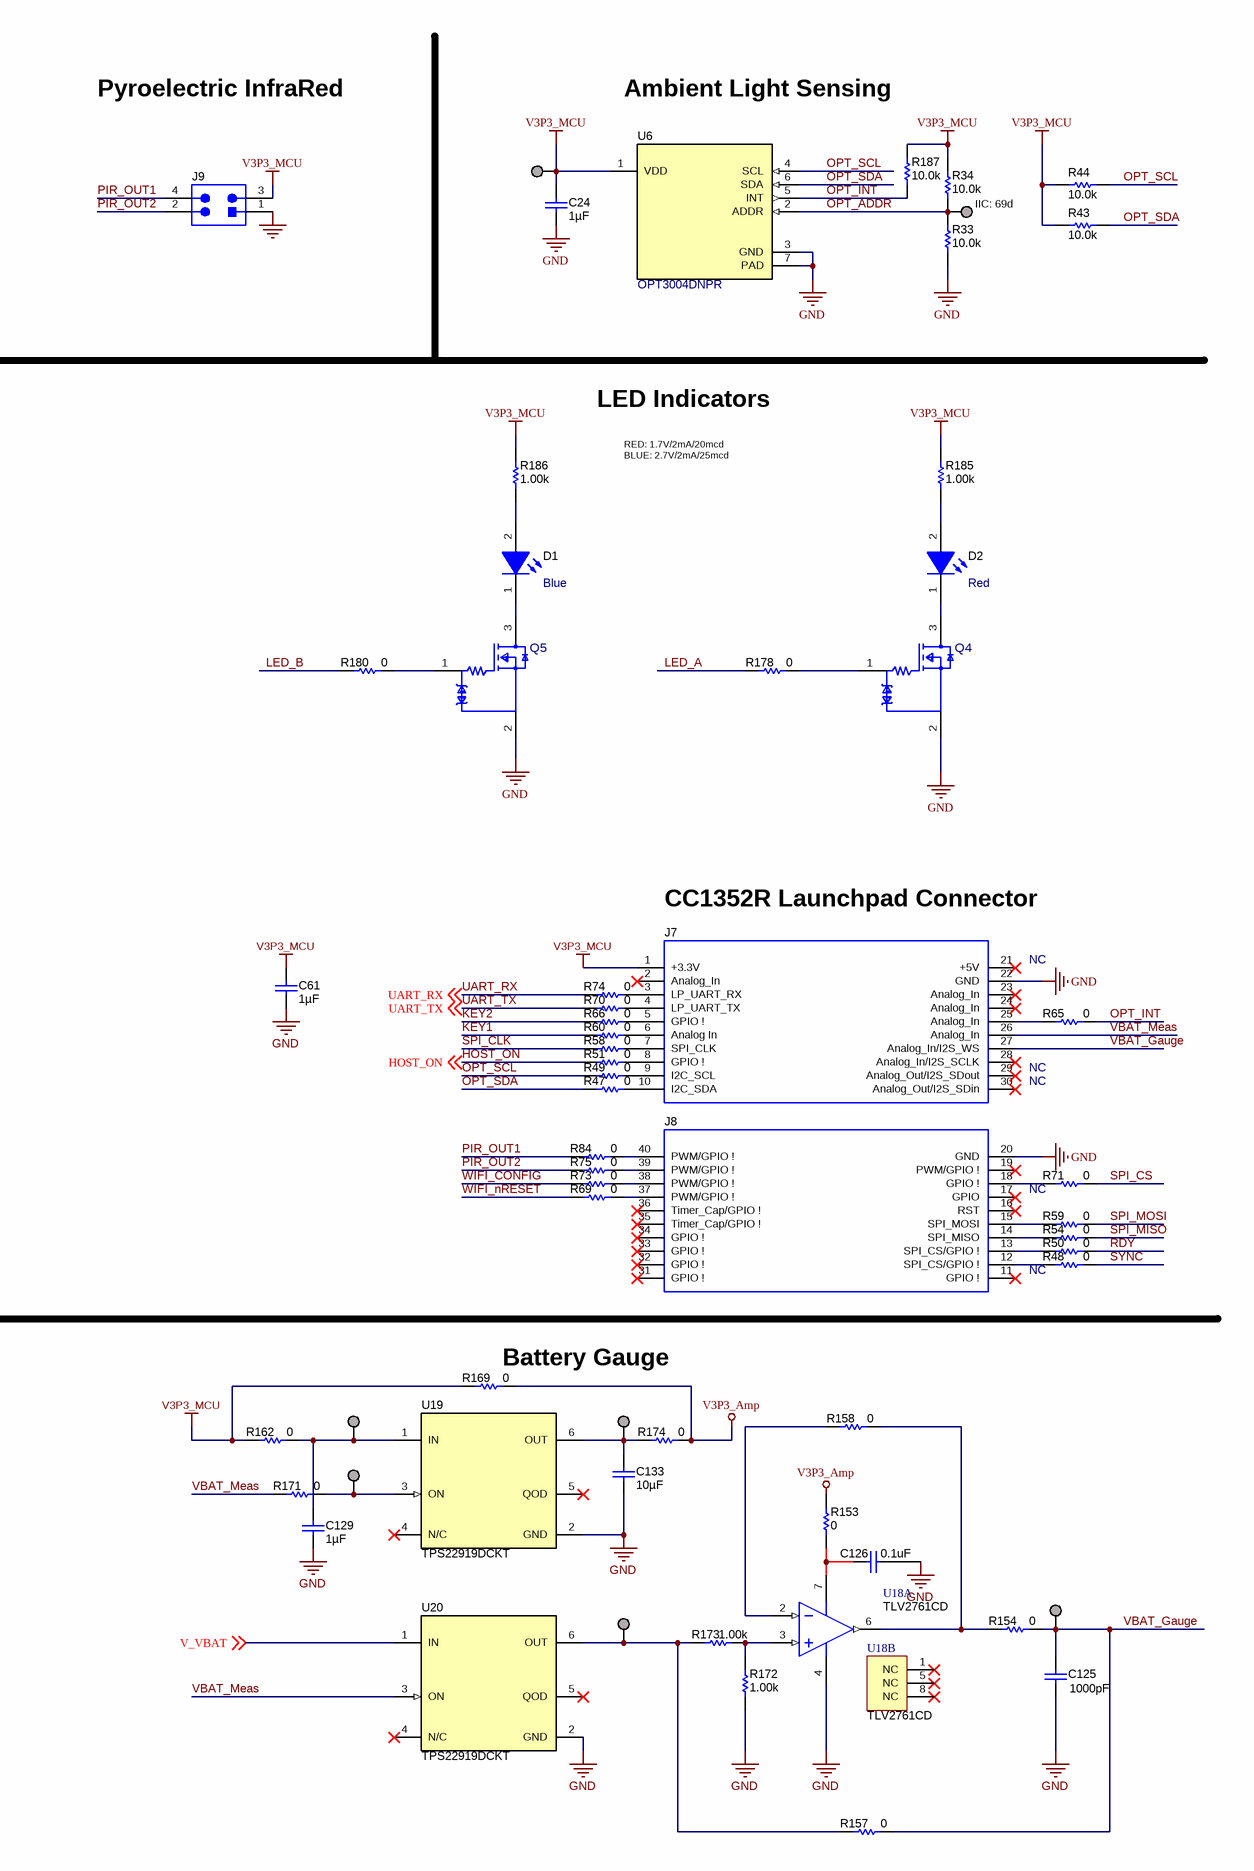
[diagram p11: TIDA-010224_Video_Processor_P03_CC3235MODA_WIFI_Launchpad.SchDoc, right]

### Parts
3.3V_MCU  TP_SM_1MM  [TP_SM_1MM]  (value not drawn)  (no BOM)
C3  value 0.1uF  [0402]  (hidden comment: GRM155R71C104KA88D)
C4  value 0.1uF  [0402]  (hidden comment: GRM155R71C104KA88D)
C5  value 0.1uF  [0402]  (hidden comment: GRM155R71C104KA88D)
C6  value 0.1uF  [0402]  (hidden comment: GRM155R71C104KA88D)
C7  ValueDisplayed: 100uF  [1210_270]  (hidden comment: C1210C107M4PAC7800)
C20  value 0.1uF  [0402]  (hidden comment: GRM155R71C104KA88D)
C22  value 0.1uF  [0402]  (hidden comment: GRM155R71C104KA88D)
C24  Cap_F: 1µF  [0603]  (hidden comment: GCM188R71C105MA64D)
C61  Cap_F: 1µF  [0603]  (hidden comment: GCM188R71C105MA64D)
C125  ValueDisplayed: 1000pF  [0402]  (hidden comment: GRM1555C1H102JA01D)
C126  value 0.1uF  [0402]  (hidden comment: GRM155R71C104KA88D)
C127  ValueDisplayed: 100uF  [1210_270]  (hidden comment: C1210C107M4PAC7800)
C129  Cap_F: 1µF  [0603]  (hidden comment: GCM188R71C105MA64D)
C133  Cap_F: 10µF  [0805_HV]  (hidden comment: CL21B106KOQNNNE)
D1  value Blue  [WL-SMCW_Blue]  (hidden comment: 150060BS75000)
D2  value Red  [WL-SMCW_RED]  (hidden comment: 150060RS75000)
D5  ESD321DPYR  [DPY0002A]
D6  ESD321DPYR  [DPY0002A]
FB1  BLM18KG121TN1D  [FP-BLM18KG121TN1D_0603-MFG]  (value not drawn)
FLASH_CLK  TP_SM_1MM  [TP_SM_1MM]  (value not drawn)  (no BOM)
FLASH_CS  TP_SM_1MM  [TP_SM_1MM]  (value not drawn)  (no BOM)
FLASH_MISO  TP_SM_1MM  [TP_SM_1MM]  (value not drawn)  (no BOM)
FLASH_MOSI  TP_SM_1MM  [TP_SM_1MM]  (value not drawn)  (no BOM)
ID  TP_SM_1MM  [TP_SM_1MM]  (value not drawn)  (no BOM)
J5  FTSH-105-01-F-D-K  [Samtec_FTSH-105-01-x-D-K]  (value not drawn)
J7  SSQ-110-03-T-D  [BoosterPack_40pin_J1J3]  (value not drawn)
J8  SSQ-110-03-T-D  [BoosterPack_40pin_J2J4]  (value not drawn)
J9  951204-8622-AR  [3M_951204-8622]  (value not drawn)
J11  61300621121  [Wurth_61300621121]  (value not drawn)
J13  TSW-105-07-G-D  [TSW-105-07-G-D]  (value not drawn)
MEAS  TP_SM_1MM  [TP_SM_1MM]  (value not drawn)  (no BOM)
MEAS_EN  TP_SM_1MM  [TP_SM_1MM]  (value not drawn)  (no BOM)
MEAS_MCU  TP_SM_1MM  [TP_SM_1MM]  (value not drawn)  (no BOM)
PS_VCC  TP_SM_1MM  [TP_SM_1MM]  (value not drawn)  (no BOM)
Q4  NTS4001NT1G  [FP-NTS4001NT1G_SC-70-MFG]  (value not drawn)
Q5  NTS4001NT1G  [FP-NTS4001NT1G_SC-70-MFG]  (value not drawn)
R1  ValueDisplayed: 0  [0603]  (hidden comment: RMCF0603ZT0R00)
R6  ValueDisplayed: 100k  [0402]  (hidden comment: ERJ-2RKF1003X)
R8  ValueDisplayed: 0  [0402S]  (hidden comment: RC0402JR-070RL)
R11  ValueDisplayed: 100k  [0402]  (hidden comment: ERJ-2RKF1003X)
R12  ValueDisplayed: 0  [0402S]  (hidden comment: RC0402JR-070RL)
R16  ValueDisplayed: 100k  [0201]  (hidden comment: RC0201FR-07100KL)
R17  ValueDisplayed: 0  [0402S]  (hidden comment: RC0402JR-070RL)
R22  ValueDisplayed: 100k  [0201]  (hidden comment: RC0201FR-07100KL)
R25  ValueDisplayed: 49.9  [0402]  (hidden comment: RC0402FR-0749R9L)
R26  ValueDisplayed: 49.9  [0402]  (hidden comment: RC0402FR-0749R9L)
R27  ValueDisplayed: 49.9  [0402]  (hidden comment: RC0402FR-0749R9L)
R28  ValueDisplayed: 49.9  [0402]  (hidden comment: RC0402FR-0749R9L)
R29  ValueDisplayed: 49.9  [0402]  (hidden comment: RC0402FR-0749R9L)
R30  ValueDisplayed: 0  [0402S]  (hidden comment: RC0402JR-070RL)
R31  ValueDisplayed: 0  [0402S]  (hidden comment: RC0402JR-070RL)
R32  ValueDisplayed: 0  [0402S]  (hidden comment: RC0402JR-070RL)
R33  ValueDisplayed: 10.0k  [0402]  (hidden comment: ERJPA2F1002X)
R34  ValueDisplayed: 10.0k  [0402]  (hidden comment: ERJPA2F1002X)
R35  ValueDisplayed: 100k  [0402]  (hidden comment: ERJ-2RKF1003X)
R36  ValueDisplayed: 100k  [0402]  (hidden comment: ERJ-2RKF1003X)
R37  ValueDisplayed: 100k  [0402]  (hidden comment: ERJ-2RKF1003X)
R38  ValueDisplayed: 100k  [0402]  (hidden comment: ERJ-2RKF1003X)
R39  ValueDisplayed: 100k  [0402]  (hidden comment: ERJ-2RKF1003X)
R40  ValueDisplayed: 100k  [0402]  (hidden comment: ERJ-2RKF1003X)
R43  ValueDisplayed: 10.0k  [0402]  (hidden comment: ERJPA2F1002X)
R44  ValueDisplayed: 10.0k  [0402]  (hidden comment: ERJPA2F1002X)
R47  ValueDisplayed: 0  [0402S]  (hidden comment: RC0402JR-070RL)
R48  ValueDisplayed: 0  [0402S]  (hidden comment: RC0402JR-070RL)
R49  ValueDisplayed: 0  [0402S]  (hidden comment: RC0402JR-070RL)
R50  ValueDisplayed: 0  [0402S]  (hidden comment: RC0402JR-070RL)
R51  ValueDisplayed: 0  [0402S]  (hidden comment: RC0402JR-070RL)
R54  ValueDisplayed: 0  [0402S]  (hidden comment: RC0402JR-070RL)
R58  ValueDisplayed: 0  [0402S]  (hidden comment: RC0402JR-070RL)
R59  ValueDisplayed: 0  [0402S]  (hidden comment: RC0402JR-070RL)
R60  ValueDisplayed: 0  [0402S]  (hidden comment: RC0402JR-070RL)
R65  ValueDisplayed: 0  [0402S]  (hidden comment: RC0402JR-070RL)
R66  ValueDisplayed: 0  [0402S]  (hidden comment: RC0402JR-070RL)
R69  value 0  [0402S]  (hidden comment: RC0402JR-070RL)
R70  ValueDisplayed: 0  [0402S]  (hidden comment: RC0402JR-070RL)
R71  ValueDisplayed: 0  [0402S]  (hidden comment: RC0402JR-070RL)
R73  ValueDisplayed: 0  [0402S]  (hidden comment: RC0402JR-070RL)
R74  ValueDisplayed: 0  [0402S]  (hidden comment: RC0402JR-070RL)
R75  ValueDisplayed: 0  [0402S]  (hidden comment: RC0402JR-070RL)
R84  ValueDisplayed: 0  [0402S]  (hidden comment: RC0402JR-070RL)
R89  ValueDisplayed: 1.00k  [0402]  (hidden comment: CRCW04021K00FKED)
R121  ValueDisplayed: 49.9  [0402]  (hidden comment: RC0402FR-0749R9L)
R133  ValueDisplayed: 10k  [0402]  (hidden comment: CRCW040210K0JNED)
R136  ValueDisplayed: 0  [0402S]  (hidden comment: RC0402JR-070RL)
R151  ValueDisplayed: 0  [0603]  (hidden comment: RMCF0603ZT0R00)
R153  ValueDisplayed: 0  [0402S]  (hidden comment: RC0402JR-070RL)
R154  ValueDisplayed: 0  [0402S]  (hidden comment: RC0402JR-070RL)
R155  ValueDisplayed: 0  [0402S]  (hidden comment: RC0402JR-070RL)
R156  ValueDisplayed: 0  [0402S]  (hidden comment: RC0402JR-070RL)
R157  ValueDisplayed: 0  [0402S]  (hidden comment: RC0402JR-070RL)
R158  ValueDisplayed: 0  [0402S]  (hidden comment: RC0402JR-070RL)
R159  ValueDisplayed: 0  [0402S]  (hidden comment: RC0402JR-070RL)
R160  ValueDisplayed: 0  [0402S]  (hidden comment: RC0402JR-070RL)
R162  ValueDisplayed: 0  [0402S]  (hidden comment: RC0402JR-070RL)
R169  ValueDisplayed: 0  [0402S]  (hidden comment: RC0402JR-070RL)
R171  ValueDisplayed: 0  [0402S]  (hidden comment: RC0402JR-070RL)
R172  ValueDisplayed: 1.00k  [0402]  (hidden comment: CRCW04021K00FKED)
R173  ValueDisplayed: 1.00k  [0402]  (hidden comment: CRCW04021K00FKED)
R174  ValueDisplayed: 0  [0402S]  (hidden comment: RC0402JR-070RL)
R175  ValueDisplayed: 0  [0402S]  (hidden comment: RC0402JR-070RL)
R176  ValueDisplayed: 0  [0402S]  (hidden comment: RC0402JR-070RL)
R177  ValueDisplayed: 0  [0402S]  (hidden comment: RC0402JR-070RL)
R178  ValueDisplayed: 0  [0402S]  (hidden comment: RC0402JR-070RL)
R180  ValueDisplayed: 0  [0402S]  (hidden comment: RC0402JR-070RL)
R185  ValueDisplayed: 1.00k  [0402]  (hidden comment: CRCW04021K00FKED)
R186  ValueDisplayed: 1.00k  [0402]  (hidden comment: CRCW04021K00FKED)
R187  ValueDisplayed: 10.0k  [0402]  (hidden comment: ERJPA2F1002X)
SW1  430152070826  [FP-430152070826_SMT_TACT-MFG]  (value not drawn)
SW2  430152070826  [FP-430152070826_SMT_TACT-MFG]  (value not drawn)
U1  CC3235MODASF12MONR  [MON0063A]
U6  OPT3004DNPR  [DNP0006A]
U18  TLV2761CD  [D0008A_N]  (parts A,B of 2)
U19  TPS22919DCKT  [DCK0006A_N]
U20  TPS22919DCKT  [DCK0006A_N]
VCC_ALS  TP_SM_1MM  [TP_SM_1MM]  (value not drawn)  (no BOM)
VCC_AMP  TP_SM_1MM  [TP_SM_1MM]  (value not drawn)  (no BOM)

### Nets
GND: C3.2 C4.1 C5.1 C6.1 C7.2 C20.1 C22.1 C24.2 C61.1 C125.2 C126.1 C127.2 C129.1 C133.2 D5.2(A) D6.2(A) J5.3 J5.5 J5.7 J5.9 J7.22(GND) J8.20(GND) J9.1 J13.9 Q4.2(Source) Q5.2(Source) R33.1 R172.1 SW1.2 SW1.4 SW2.2 SW2.4 U1.1(GND) U1.2(GND) U1.16(GND) U1.25(GND) U1.26(GND) U1.27(GND) U1.28(GND) U1.29(GND) U1.30(GND) U1.32(GND) U1.38(GND) U1.43(GND) U1.55(GND) U1.56(GND) U1.57(GND) U1.58(GND) U1.59(GND) U1.60(GND) U1.61(GND) U1.62(GND) U1.63(GND) U6.3(GND) U6.7(PAD) U18.4(GND) U19.2(GND) U20.2(GND)
V3P3_Amp: R153.2 R169.2 R174.2
V3P3_MCU: 3.3V_MCU.1 C3.1 C4.2 C5.2 C6.2 C7.1 C24.1 C61.2 C127.1 FB1.2 J7.1(+3.3V) J9.3 R1.1 R6.1 R11.1 R16.2 R22.2 R34.2 R35.1 R36.1 R37.1 R38.1 R39.1 R40.1 R43.1 R44.1 R89.1 R133.1 R151.1 R162.1 R169.1 R185.2 R186.2 R187.2 U1.37(VBAT1) U1.40(VBAT2) U6.1(VDD) VCC_ALS.1
V3P3A: FB1.1
DEBUG_MAC: J13.4 U1.50(GPIO_05)
DEBUG_NWP: J13.2 U1.51(GPIO_06)
HOST_ON: R51.1 R160.2 ; off-sheet HOST_ON
IR_CUT_EN: R159.2 ; off-sheet IR_CUT_EN
IR_LED_EN: R176.2 ; off-sheet IR_LED_EN
KEY1: C20.2 D5.1(K) J13.6 R16.1 R60.1 SW1.1 SW1.3
KEY2: C22.2 D6.1(K) J13.8 R22.1 R66.1 SW2.1 SW2.3
LED_A: R178.1 U1.53(GPIO_08)
LED_B: R180.1 U1.52(GPIO_07)
LED_PWM: R17.2 ; off-sheet LED_PWM
OPT_ADDR: ID.1 R33.2 R34.1 U6.2(ADDR)
OPT_INT: R32.2 R65.2 R187.1 U6.5(INT)
OPT_SCL: R31.2 R44.2 R49.1 U6.4(SCL)
OPT_SDA: R30.2 R43.2 R47.1 U6.6(SDA)
P16_JTAG_TDI: J5.8 U1.12(JTAG_TDI)
P17_JTAG_TDO: J5.6 U1.18(JTAG_TDO)
P19_JTAG_TCK: J5.4 U1.21(JTAG_TCK)
P20_JTAG_TMS: J5.2 U1.22(JTAG_TMS)
PIR_OUT1: J9.4 R84.1 R136.2
PIR_OUT2: J9.2 R75.1 R177.2
RDY: R25.2 R39.2 R50.2 ; off-sheet RDY
SI0: J11.2 U1.34(SOP0)
SI1: J11.4 U1.24(SOP1)
SI2: J11.6 U1.23(SOP2)
SN_IR_IN1: R156.2 ; off-sheet SN_IR_IN1
SN_IR_IN2: R155.2 ; off-sheet SN_IR_IN2
SPI_CLK: R29.2 R36.2 R58.1 ; off-sheet SPI_CLK
SPI_CS: R27.2 R35.2 R71.2 ; off-sheet SPI_CS
SPI_MISO: R37.2 R54.2 R121.2 ; off-sheet SPI_MISO
SPI_MOSI: R28.2 R38.2 R59.2 ; off-sheet SPI_MOSI
SYNC: R26.2 R40.2 R48.2 ; off-sheet SYNC
UART_RX: J13.5 R11.2 R12.2 R74.1 ; off-sheet UART_RX
UART_TX: J13.3 R6.2 R8.2 R70.1 ; off-sheet UART_TX
V_VBAT: U20.1(IN) ; off-sheet V_VBAT
VBAT_Gauge: C125.1 J7.27(Analog_In/I2S_WS) MEAS_MCU.1 R154.2 R157.2
VBAT_Meas: J7.26(Analog_In) R171.1 U20.3(ON)
WIFI_CONFIG: J13.10 R73.1 R136.1 U1.54(GPIO_09)
WIFI_nRESET: J13.7 R69.1 R175.1
NetC126_2: C126.2 R153.1 U18.7(VDD)
NetC129_2: C129.2 PS_VCC.1 R162.2 U19.1(IN)
NetC133_1: C133.1 R174.1 U19.6(OUT) VCC_AMP.1
NetD1_1: D1.1(K) Q5.3(Drain)
NetD1_2: D1.2(A) R186.1
NetD2_1: D2.1(K) Q4.3(Drain)
NetD2_2: D2.2(A) R185.1
NetFLASH_CLK_1: FLASH_CLK.1 U1.15(FLASH_SPI_CLK)
NetFLASH_CS_1: FLASH_CS.1 U1.14(FLASH_SPI_~{CS}_IN)
NetFLASH_MISO_1: FLASH_MISO.1 U1.13(FLASH_SPI_MISO)
NetFLASH_MOSI_1: FLASH_MOSI.1 U1.17(FLASH_SPI_MOSI)
NetJ5_1: J5.1 R89.2
NetJ7_3: J7.3(LP_UART_RX) R74.2
NetJ7_4: J7.4(LP_UART_TX) R70.2
NetJ7_5: J7.5(GPIO_!) R66.2
NetJ7_6: J7.6(Analog_In) R60.2
NetJ7_7: J7.7(SPI_CLK) R58.2
NetJ7_8: J7.8(GPIO_!) R51.2
NetJ7_9: J7.9(I2C_SCL) R49.2
NetJ7_10: J7.10(I2C_SDA) R47.2
NetJ7_25: J7.25(Analog_In) R65.1
NetJ8_12: J8.12(SPI_CS/GPIO_!) R48.1
NetJ8_13: J8.13(SPI_CS/GPIO_!) R50.1
NetJ8_14: J8.14(SPI_MISO) R54.1
NetJ8_15: J8.15(SPI_MOSI) R59.1
NetJ8_18: J8.18(GPIO_!) R71.1
NetJ8_37: J8.37(PWM/GPIO_!) R69.2
NetJ8_38: J8.38(PWM/GPIO_!) R73.2
NetJ8_39: J8.39(PWM/GPIO_!) R75.2
NetJ8_40: J8.40(PWM/GPIO_!) R84.2
NetJ11_1: J11.1 J11.3 J11.5 R133.2
NetJ13_1: J13.1 R151.2
NetMEAS_1: MEAS.1 R157.1 R173.1 U20.6(OUT)
NetMEAS_EN_1: MEAS_EN.1 R171.2 U19.3(ON)
NetQ4_1: Q4.1(Gate) R178.2
NetQ5_1: Q5.1(Gate) R180.2
NetR1_2: R1.2 U1.36(VBAT_RESET)
NetR8_1: R8.1 U1.46(GPIO_01)
NetR12_1: R12.1 U1.47(GPIO_02)
NetR17_1: R17.1 U1.19(GPIO_28)
NetR25_1: R25.1 U1.4(GPIO_11)
NetR26_1: R26.1 U1.3(GPIO_10)
NetR27_1: R27.1 U1.8(GPIO_17)
NetR28_1: R28.1 U1.7(GPIO_16)
NetR29_1: R29.1 U1.5(GPIO_14)
NetR30_1: R30.1 U1.11(GPIO_22)
NetR31_1: R31.1 U1.10(GPIO_13)
NetR32_1: R32.1 U1.9(GPIO_12)
NetR121_1: R121.1 U1.6(GPIO_15)
NetR154_1: R154.1 R158.2 U18.6(OUT)
NetR155_1: R155.1 U1.49(GPIO_04)
NetR156_1: R156.1 U1.48(GPIO_03)
NetR158_1: R158.1 U18.2(IN-)
NetR159_1: R159.1 R160.1 U1.44(GPIO_0)
NetR172_2: R172.2 R173.2 U18.3(IN+)
NetR175_2: R175.2 U1.35(~{RESET})
NetR176_1: R176.1 R177.1 U1.42(GPIO_30)

Not connected (* = marked no-connect by the designer): J5 10*; J7 2(Analog_In)* 21(+5V)* 23(Analog_In)* 24(Analog_In)* 28(Analog_In/I2S_SCLK)* 29(Analog_Out/I2S_SDout)* 30(Analog_Out/I2S_SDin)*; J8 11(GPIO_!)* 16(RST)* 17(GPIO)* 19(PWM/GPIO_!)* 31(GPIO_!)* 32(GPIO_!)* 33(GPIO_!)* 34(GPIO_!)* 35(Timer_Cap/GPIO_!)* 36(Timer_Cap/GPIO_!)*; U1 20(NC)* 31(RF_ABG)* 33(NC)* 39(NC)* 41(NC)* 45(NC)*; U18 1(NC)* 5(NC)* 8(NC)*; U19 4(N/C)* 5(QOD)*; U20 4(N/C)* 5(QOD)*

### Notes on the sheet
- Wi-Fi Module
- Pyroelectric InfraRed
- Ambient Light Sensing
- (near ID) IIC: 69d
- LED Indicators
- RED: 1.7V/2mA/20mcd
  BLUE: 2.7V/2mA/25mcd
- (near J11) Populate 3-4 header for SI1
- (near U1) CC3235MOD WIFI MCU
- CC1352R Launchpad Connector
- NC
- JTAG Connector
- Buttons
- KEY 1
- WPS Button (back side)
- KEY 2
- Front Door Button
- (near R71) NC
- (near J13) Debug Connector
- (near R169) Battery Gauge

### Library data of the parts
3.3V_MCU FLASH_CLK FLASH_CS FLASH_MISO FLASH_MOSI ID MEAS MEAS_EN MEAS_MCU PS_VCC VCC_ALS VCC_AMP = CMP-0003825-1: 1mm Test Point, SMT; Manufacturer: Any
C3-C6 C20 C22 C126 = Cap: as C29 on sheet TIDA-010224_Video_Processor_P02_OA7000_Image_Sensor
C7 C127 = CMP-0009081-1: CAP, CERM, 100 uF, 16 V, +/- 20%, X5R, 1210; Manufacturer: Kemet; TaMin_C: -55°C; Polarized: N; SizeAreaWB_mm2: 14.7; Value1: Unknown; U/M: EA; Value: 100uF; TaMax_C: 85°C; SizeZ_mm: 2.7; SizeX_mm: 3.2; SizeY_mm: 2.5; Cap_Case: 1210; Value2: 16V; SizeArea_mm2: 8; Cap_F: 100µF; AEC Category: Q200
C24 C61 C129 = CMP-0007137-1: as C33 on sheet TIDA-010224_Video_Processor_P02_OA7000_Image_Sensor
C125 = CMP-0006412-1: CAP, CERM, 1000 pF, 50 V, +/- 5%, C0G/NP0, 0402; Manufacturer: MuRata; TaMin_C: -55°C; Polarized: N; SizeAreaWB_mm2: 3; Value1: Unknown; U/M: EA; Value: 1000pF; TaMax_C: 125°C; SizeZ_mm: 0.6; SizeX_mm: 1; SizeY_mm: 0.5; Value2: 50V; Cap_F: 1nF; AEC Category: Q200
C133 = CMP-0007995-1: as C31 on sheet TIDA-010224_Video_Processor_P02_OA7000_Image_Sensor
D1 = CMP-0002946-3: LED, Blue, SMD; Manufacturer: Wurth Elektronik; Power_TotalModule: 105mW; Angle: 140; Tjmax_C: 85°C; Vf_V: 3.2V; Io_A: 30mA; Value1: 0.105W; Vr_V: 5V; Type: InGaN
D2 = CMP-0002947-3: LED, Red, SMD; Manufacturer: Wurth Elektronik; Value1: 0.072W; Vf_V: 2V; Angle: 140; Tjmax_C: 85°C; Type: AlInGaP; Vr_V: 5V; Io_A: 30mA; Power_TotalModule: 72mW
D5 D6 = CMP-0860710-3: 1-channel 30 kV ESD protection diode with low capacitance (< 1pF) in 0402 package, DPY0002A (X1SON-2); Manufacturer: Texas Instruments; CompType: IC; SizeY_mm: 0.6; SizeAreaWB_mm2: 3.2; SizeZ_mm: 0.45; AEC Category: Q200; AEC Qualified: N; Rating: Catalog; SizeX_mm: 1
FB1 = CMP-0089995-1: as FB3 on sheet TIDA-010224_Video_Processor_P02_OA7000_Image_Sensor
J5 = CMP-0075533-1: Header, 1.27 mm, 5x2, Gold, TH; Manufacturer: Samtec; Pitch_mm: 1.27; Gender: Male; Green_REACh: Passed; CT: False; Shrouded: Y; Green_Lifecycle: Active; Row_Count: 2
J7 = CMP-0003837-4: Receptacle, 2.54mm, 10x2, Tin, TH; Alternate PartNumber: CRD-081413-A-G; Manufacturer: Samtec; Alternate Manufacturer: Major League Electronics; Note: Booster Pack 40 pin J1 and J3; Green_Lifecycle: Active; Green_REACh: Incomplete
J8 = CMP-0078266-4: Receptacle, 2.54mm, 10x2, Tin, TH; Alternate PartNumber: CRD-081413-A-G; Manufacturer: Samtec; Alternate Manufacturer: Major League Electronics; Note: Booster Pack 40 pin J2 and J4; Green_REACh: Incomplete; Green_Lifecycle: Active
J9 = CMP-0075359-1: Header, 2mm, 2x2, Gold, TH; Manufacturer: 3M; CNHeader: True; Current_A: 1A; Shrouded: N; Gender: Male; Voltage_V: 1kV; Row_Count: 2; CT: False; Cert_UL: Y
J11 = CMP-0054802-1: Header, 2.54mm, 3x2, Gold, TH; Manufacturer: Wurth Elektronik; CNHeader: TRUE; Green_Lifecycle: Active; Shrouded: N; Gender: Male; Green_REACh: Passed; Row_Count: 2; RowSpacing_mm: 2.54; CT: FALSE
J13 = CMP-0075410-1: Header, 100mil, 5x2, Gold, TH; Manufacturer: Samtec; Pitch_mm: 2.54; Cert_VDE: N; Gender: Male; Cert_CSA: Y; Voltage_V: 550V; Green_REACh: Passed; Current_A: 6.3A; CT: False; Green_Lifecycle: Active; Row_Count: 2; CNHeader: True
Q4 Q5 = CMP-0089424-1: as Q2 on sheet TIDA-010224_Video_Processor_P02_OA7000_Image_Sensor
R1 R151 = CMP-0023343-2: RES, 0, 1%, 0.1 W, AEC-Q200 Grade 0, 0603; Manufacturer: Stackpole Electronics Inc; Power_W: 100mW; TempCo: ppm/C; U/M: EA; Value: 0; SizeX_mm: 1.6; SizeY_mm: 0.8; SizeZ_mm: 1; Value2: 0.1W; SizeArea_mm2: 1.28; AEC Qualified: Y; AEC Category: Q200
R6 R11 R35-R40 = CMP-0026659-2: RES, 100 k, 1%, 0.1 W, 0402; Manufacturer: Panasonic; U/M: EA; Value2: 0.1W; EIA_Code: E96; Value: 100k; SizeArea_mm2: 0.5; TempCo: 100 ppm/C; SizeZ_mm: 0.6; AEC Category: Q200; VDC_V: 50V; Power_W: 100mW; AEC Grade: 0; SizeX_mm: 1; AEC Qualified: Yes
R8 R12 R17 R30-R32 R47-R51 R54 R58-R60 R65 R66 R70 R71 R73-R75 R84 R136 R153-R160 R162 R169 R171 R174-R178 R180 = CMP-0027004-2: as R21 on sheet TIDA-010224_Video_Processor_P02_OA7000_Image_Sensor
R16 R22 = CMP-0027293-2: as R96-R98 on sheet TIDA-010224_Video_Processor_P02_OA7000_Image_Sensor
R25-R29 R121 = CMP-0026738-1: RES, 49.9, 1%, 0.063 W, 0402; Manufacturer: Yageo America; Power_W: 63mW; TempCo: 100 ppm/C; Value_Code: 49R9; U/M: EA; Value: 49.9; EIA_Code: E96; SizeX_mm: 1; SizeY_mm: 0.5; SizeZ_mm: 0.6; Value2: 0.063W; AEC Qualified: N; VDC_V: 50V; AEC Category: Q200
R33 R34 R43 R44 R187 = CMP-0078779-1: as R15 on sheet TIDA-010224_Video_Processor_P02_OA7000_Image_Sensor
R69 = CMP-0027004-2: RES, 0, 5%, 0.063 W, 0402; Manufacturer: Yageo America; Power_W: 63mW; TempCo: 200 ppm/C; Value_Code: 0000; U/M: EA; EIA_Code: E24; SizeX_mm: 1; SizeY_mm: 0.5; SizeZ_mm: 0.6; Value2: 0.063W; VDC_V: 50V; AEC Category: Q200
R89 R172 R173 R185 R186 = CMP-0026071-3: as R55-R57 on sheet TIDA-010224_Video_Processor_P02_OA7000_Image_Sensor
R133 = CMP-0026825-5: RES, 10 k, 5%, 0.063 W, AEC-Q200 Grade 0, 0402; Manufacturer: Vishay-Dale; Power_W: 63mW; TempCo: 200 ppm/C; Value_Code: 10k0; Value: 10k; EIA_Code: E24; SizeX_mm: 1; SizeY_mm: 0.5; SizeZ_mm: 0.6; Value2: 0.063W; AEC Qualified: Y; VDC_V: 50V; AEC Category: Q200; AEC Grade: 0
SW1 SW2 = CMP-0089991-1: Tactile Switch SPST-NO Top Actuated Surface Mount; Manufacturer: Wurth Electronics; VDC_V: 12V; Coil Resistance_ohm: 100mΩ; SizeZ_mm: 7.15mm; AEC Qualified: No; Operating Force: 260gf; Electromechanical Life: 200000Cycles; Contact Current Rating: 50mA
U1 = CMP-0085201-1: SimpleLink Wi-FI and Internet-of-Things Dual Band Module Solution, a Single-Chip Wireless MCU, MON0063A (QFM-63); Manufacturer: Texas Instruments; SizeY_mm: 20.5; AEC Qualified: N; SizeX_mm: 25.5; AEC Category: Q200; SizeAreaWB_mm2: 618.75; SizeArea_mm2: 522.75; CompType: IC; SizeZ_mm: 2.45
U6 = CMP-0085872-1: Ambient Light Sensor (ALS), DNP0006A (USON-6); Alternate PartNumber: OPT3004DNPT; Manufacturer: Texas Instruments; SizeAreaWB_mm2: 9; AEC Qualified: N; CompType: IC; SizeY_mm: 2; SizeZ_mm: 0.65; AEC Category: Q200; SizeArea_mm2: 4
U18 = CMP-0042724-1: Single MicroPower, Rail-to-Rail, Single Supply Amplifier, 1.8 to 3.6 V, 0 to 70 degC, 8-pin SOIC (D8), Green (RoHS & no Sb/Br); Manufacturer: Texas Instruments; Packing: TUBE; Offset Drift(Typ)(uV/C): 9; CMRR(Min)(dB): 50; Total Supply Voltage(Max)(+5V is 5, +/-5V is 10): 3.6; Slew Rate(Typ)(V/us): 0.2; Sub Family: Low Power Amp (<=500uA), Low Supply Voltage Amplifier (<=2.7V), Precision Amplifier; Number of Channels: 1; Vio (25C)(Max)(mV): 3.5; IIB(Max)(pA): 15; Total Supply Voltage(Min)(+5V is 5, +/-5V is 10): 1.8; GBW(Typ)(MHz): 0.5; Iq per channel(Max)(mA): 0.028; Rating: Catalog
U19 U20 = CMP-0081107-1: 5.5-V, 1.5-A, 100-mohm Load Switch with Output Discharge, DCK0006A (SOT-SC70-6); Alternate PartNumber: TPS22919DCKR; Alternate Manufacturer: Texas Instruments; SizeAreaWB_mm2: 9.3; SizeZ_mm: 1.1; SizeX_mm: 2.1; SizeY_mm: 2; SizeArea_mm2: 4.2; CompType: IC; AEC Qualified: N; AEC Category: Q200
